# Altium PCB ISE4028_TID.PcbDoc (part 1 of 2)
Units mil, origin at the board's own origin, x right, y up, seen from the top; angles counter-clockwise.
Board outline 4000 x 3450 mil, 4 copper layers (Layer 1 - Top Layer, Layer 2 - GND, Layer 3 - PWR, Layer 4 - Bottom Layer), stack 61.434 mil thick; 151 components, 89 nets, 421 pads, 328 vias.
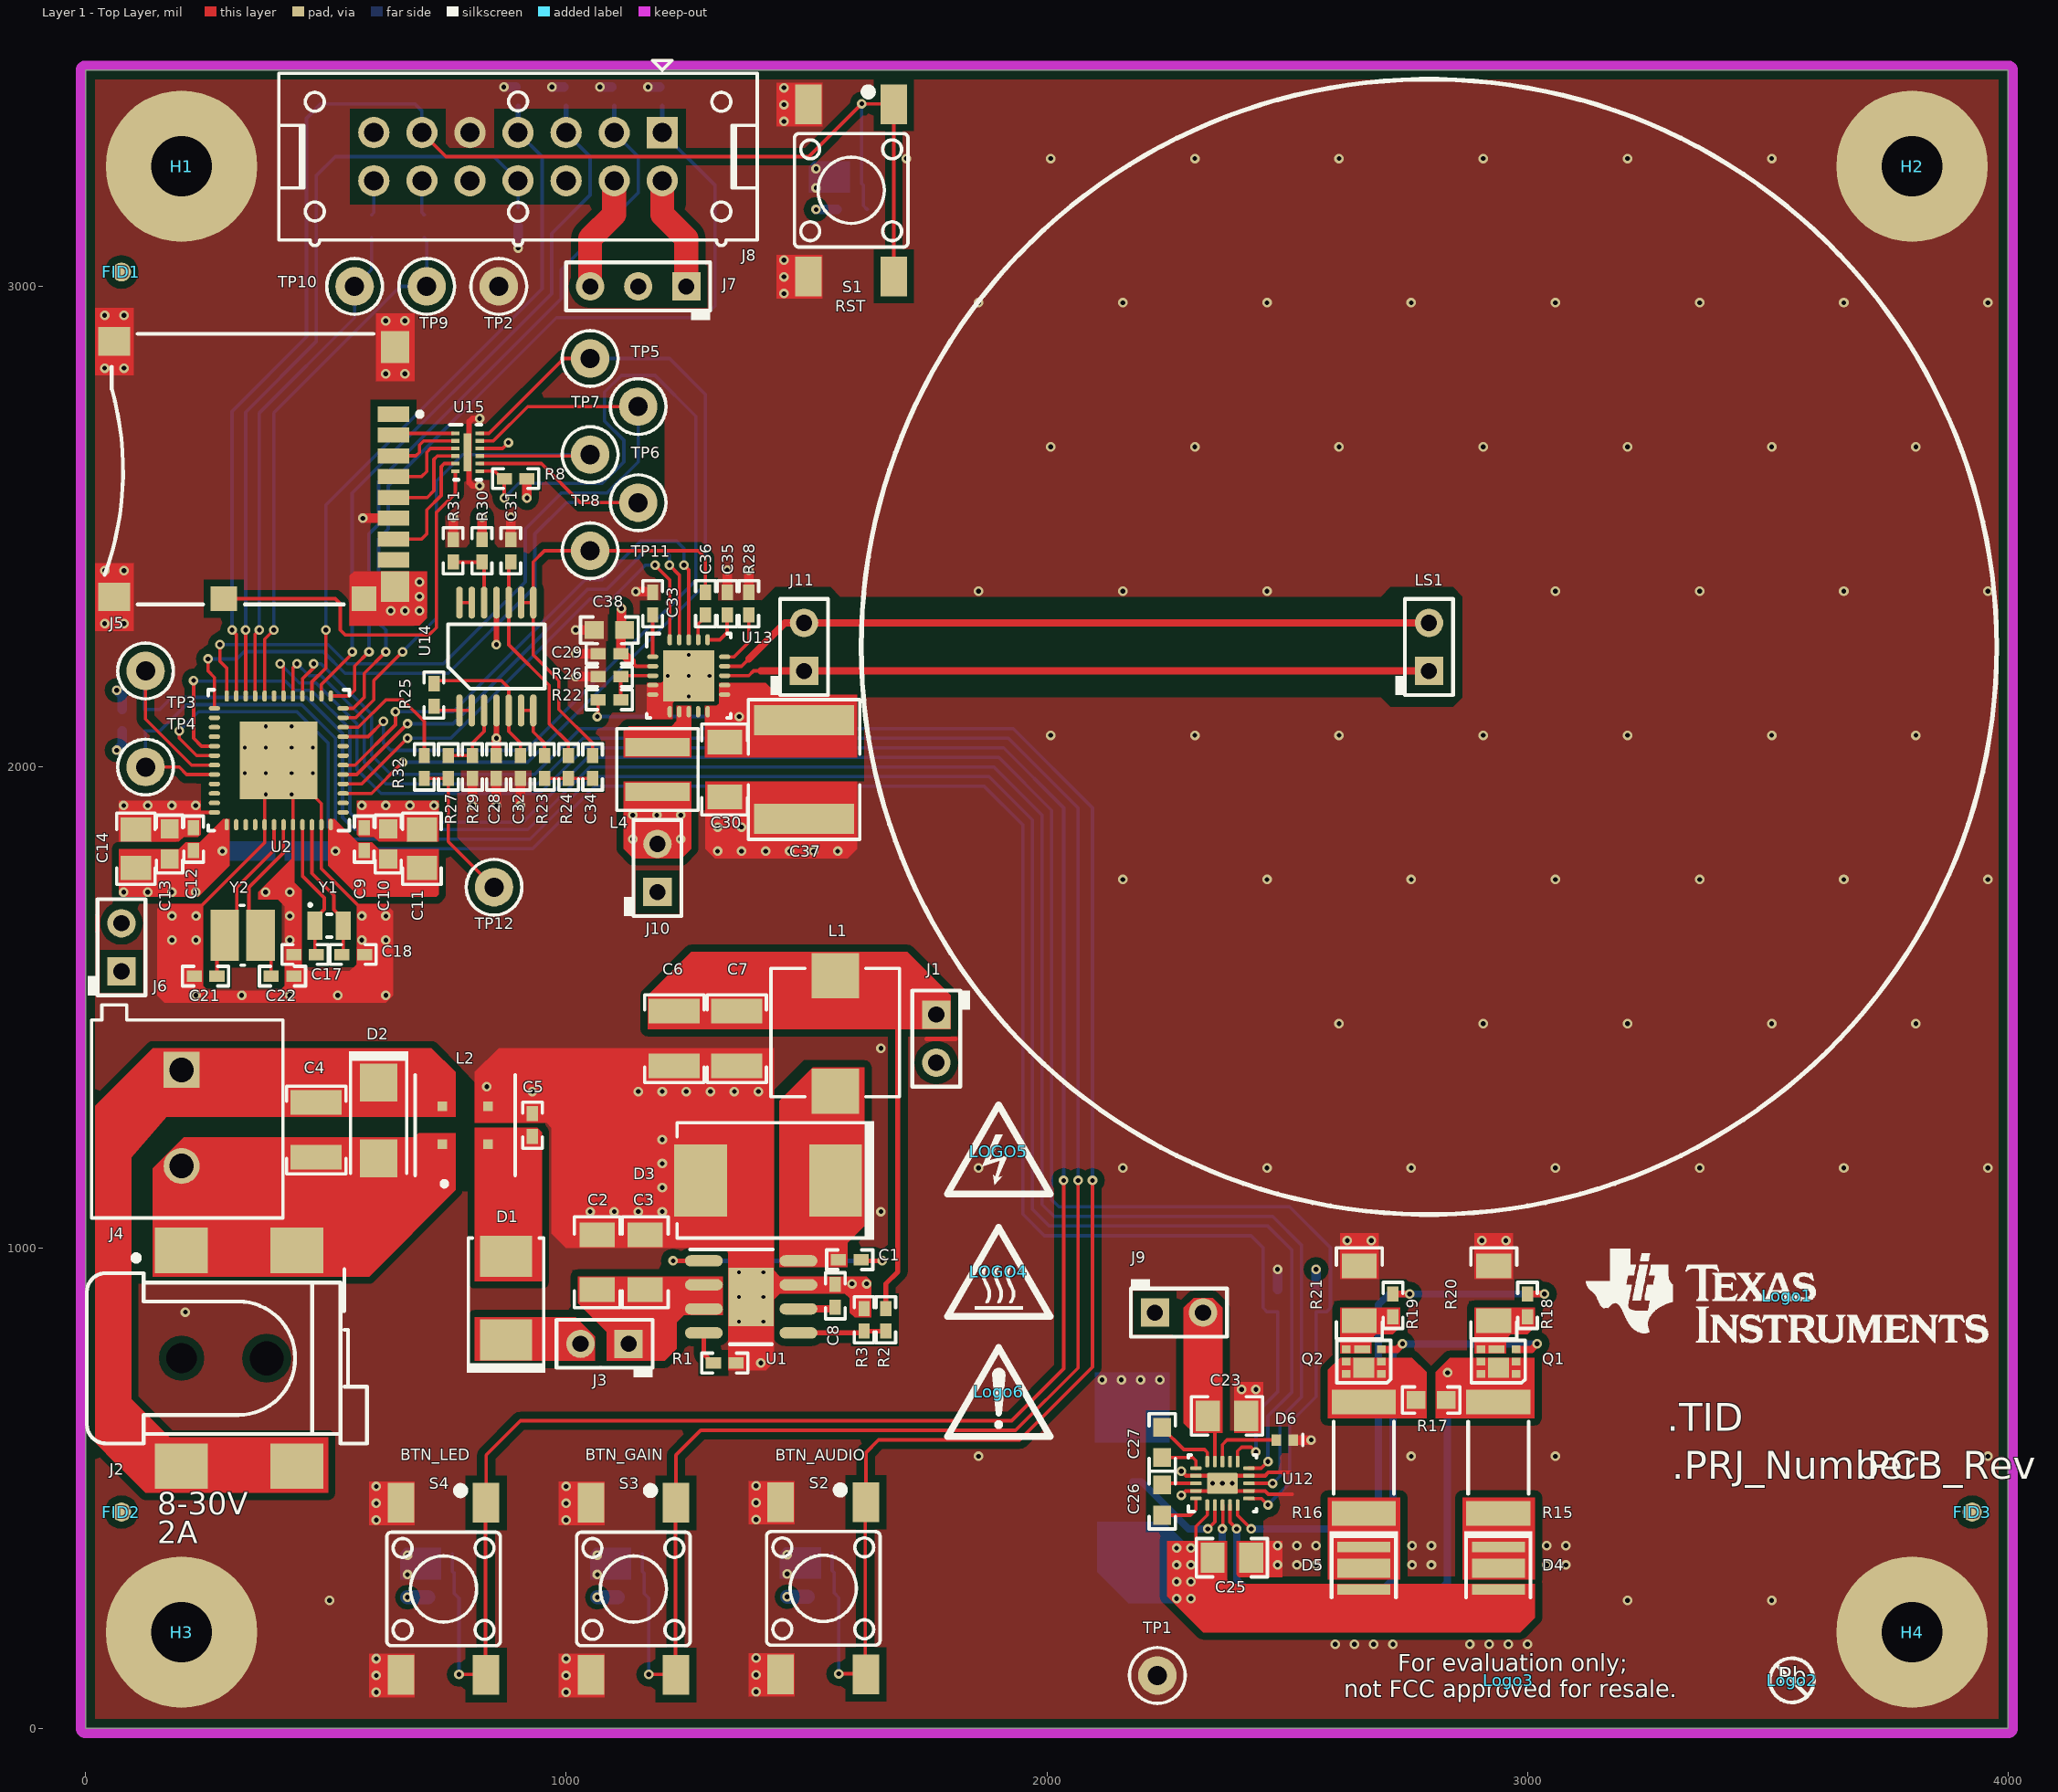
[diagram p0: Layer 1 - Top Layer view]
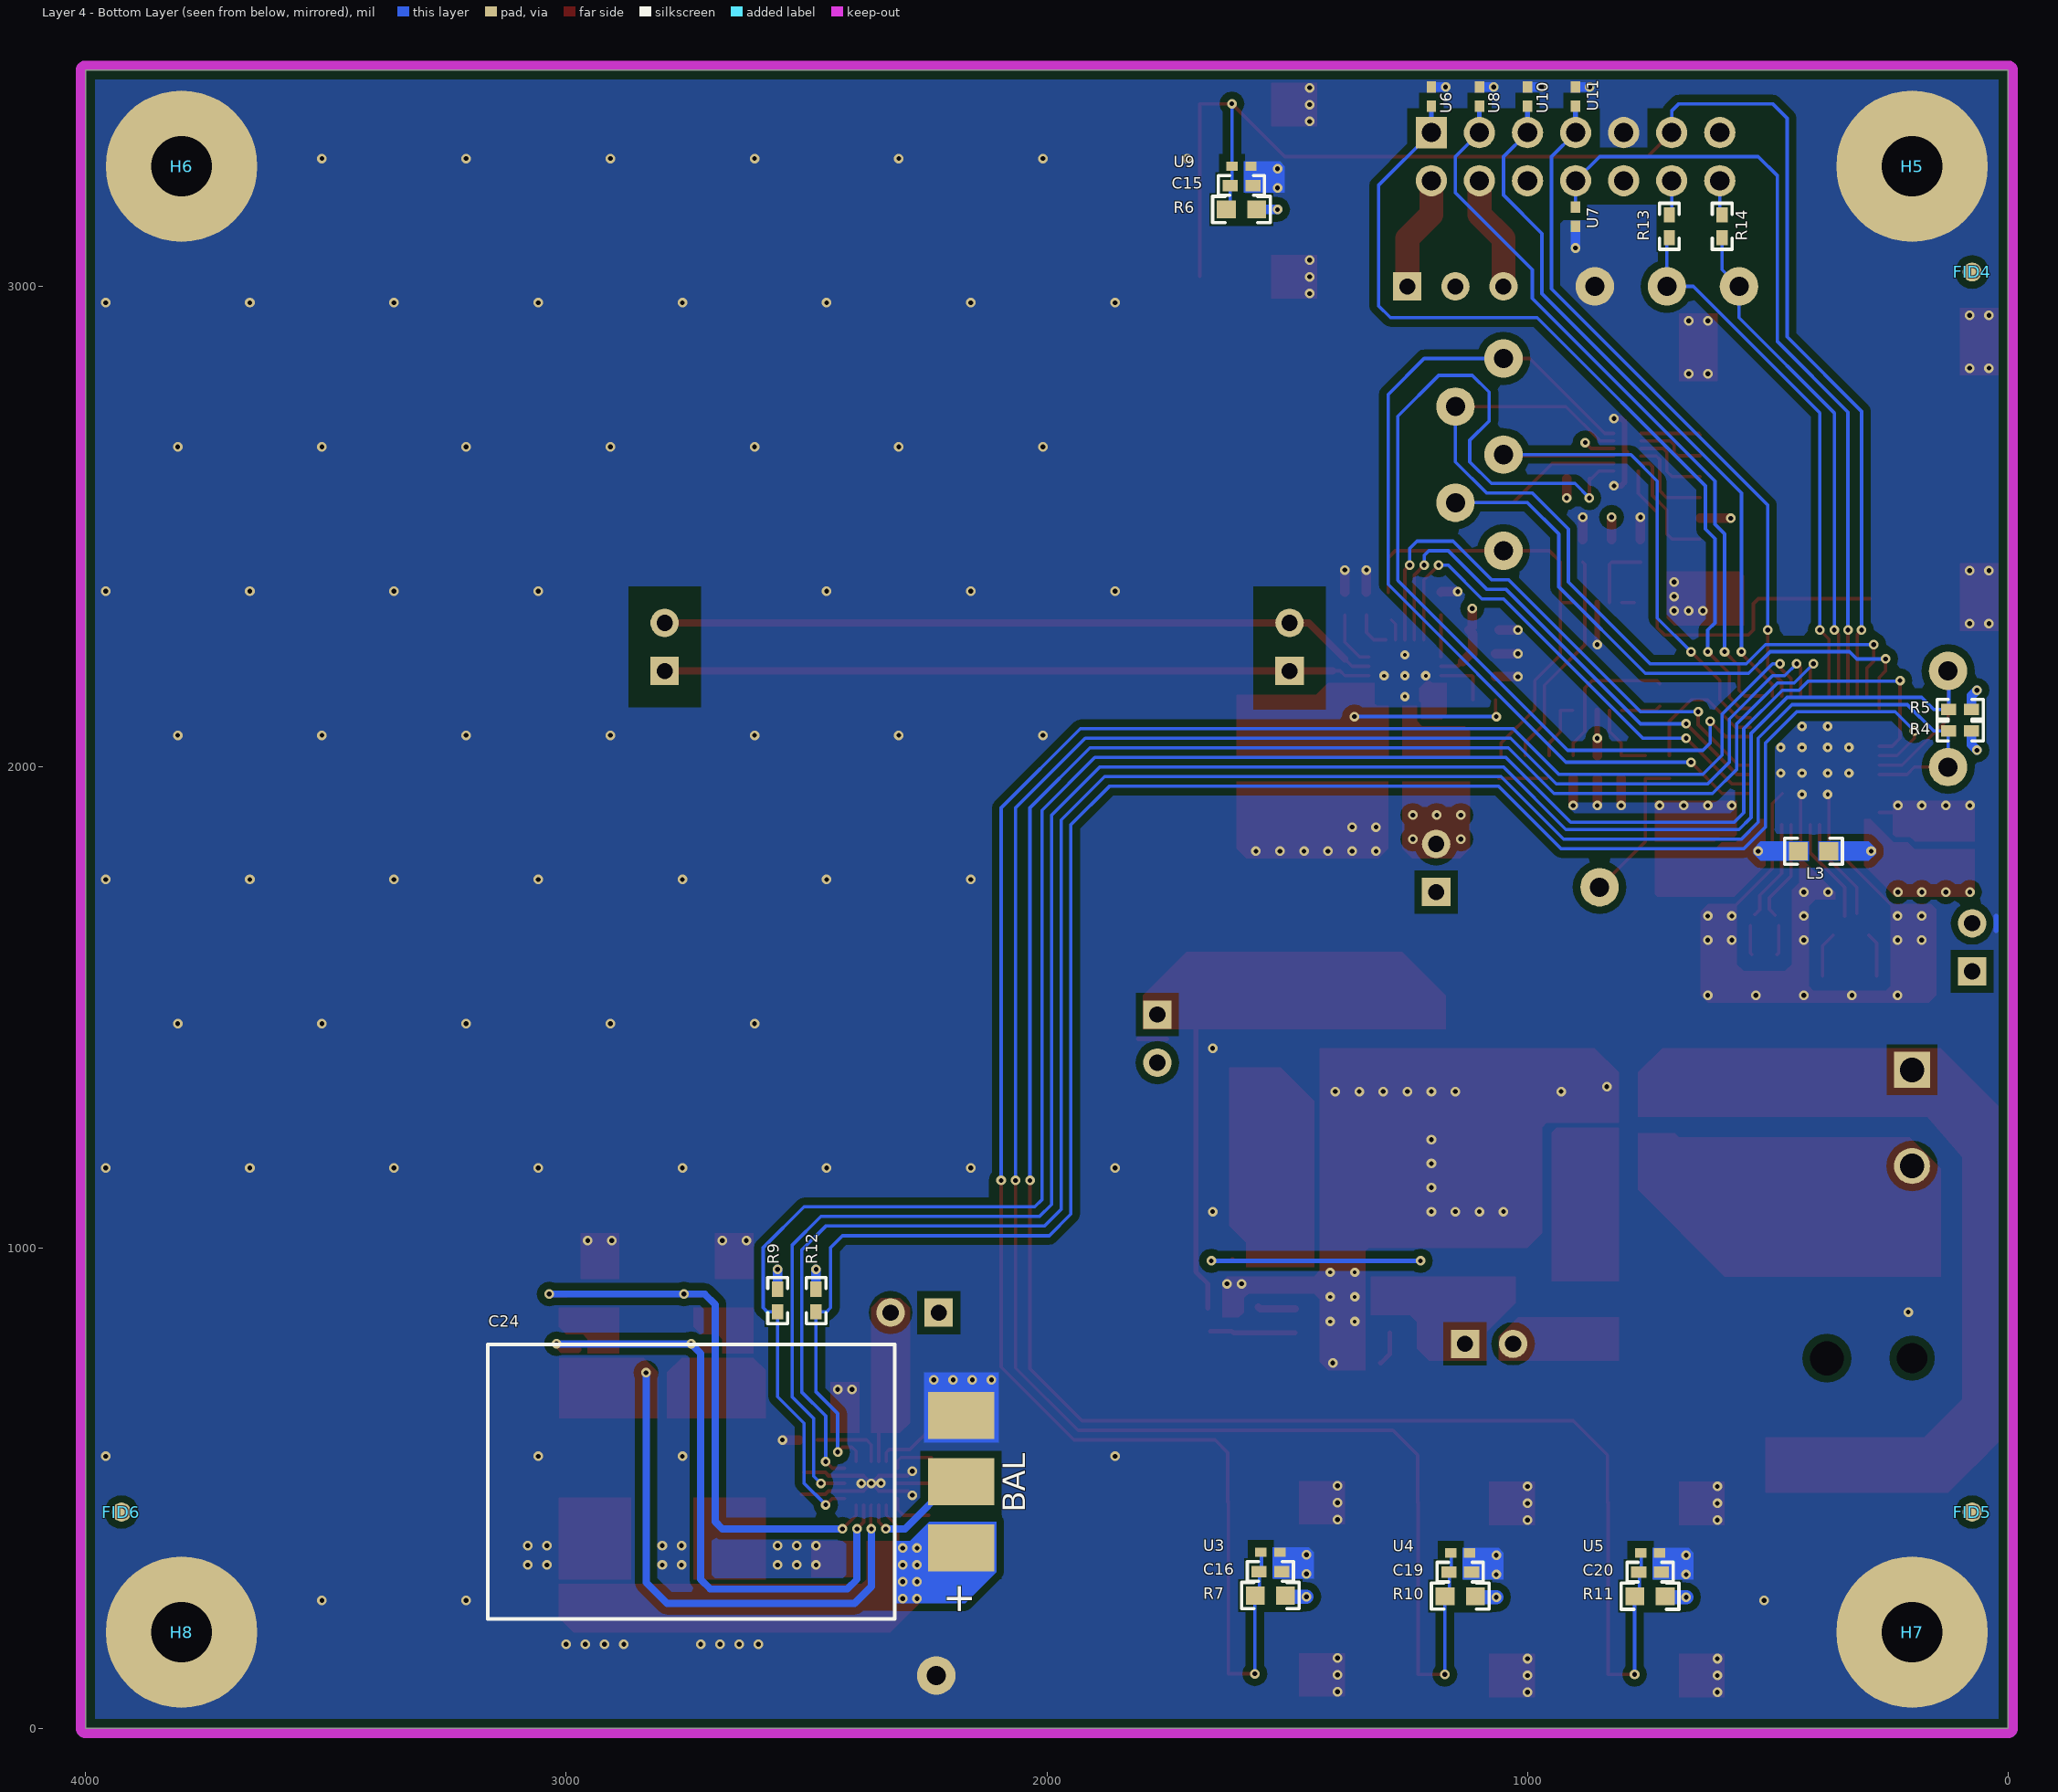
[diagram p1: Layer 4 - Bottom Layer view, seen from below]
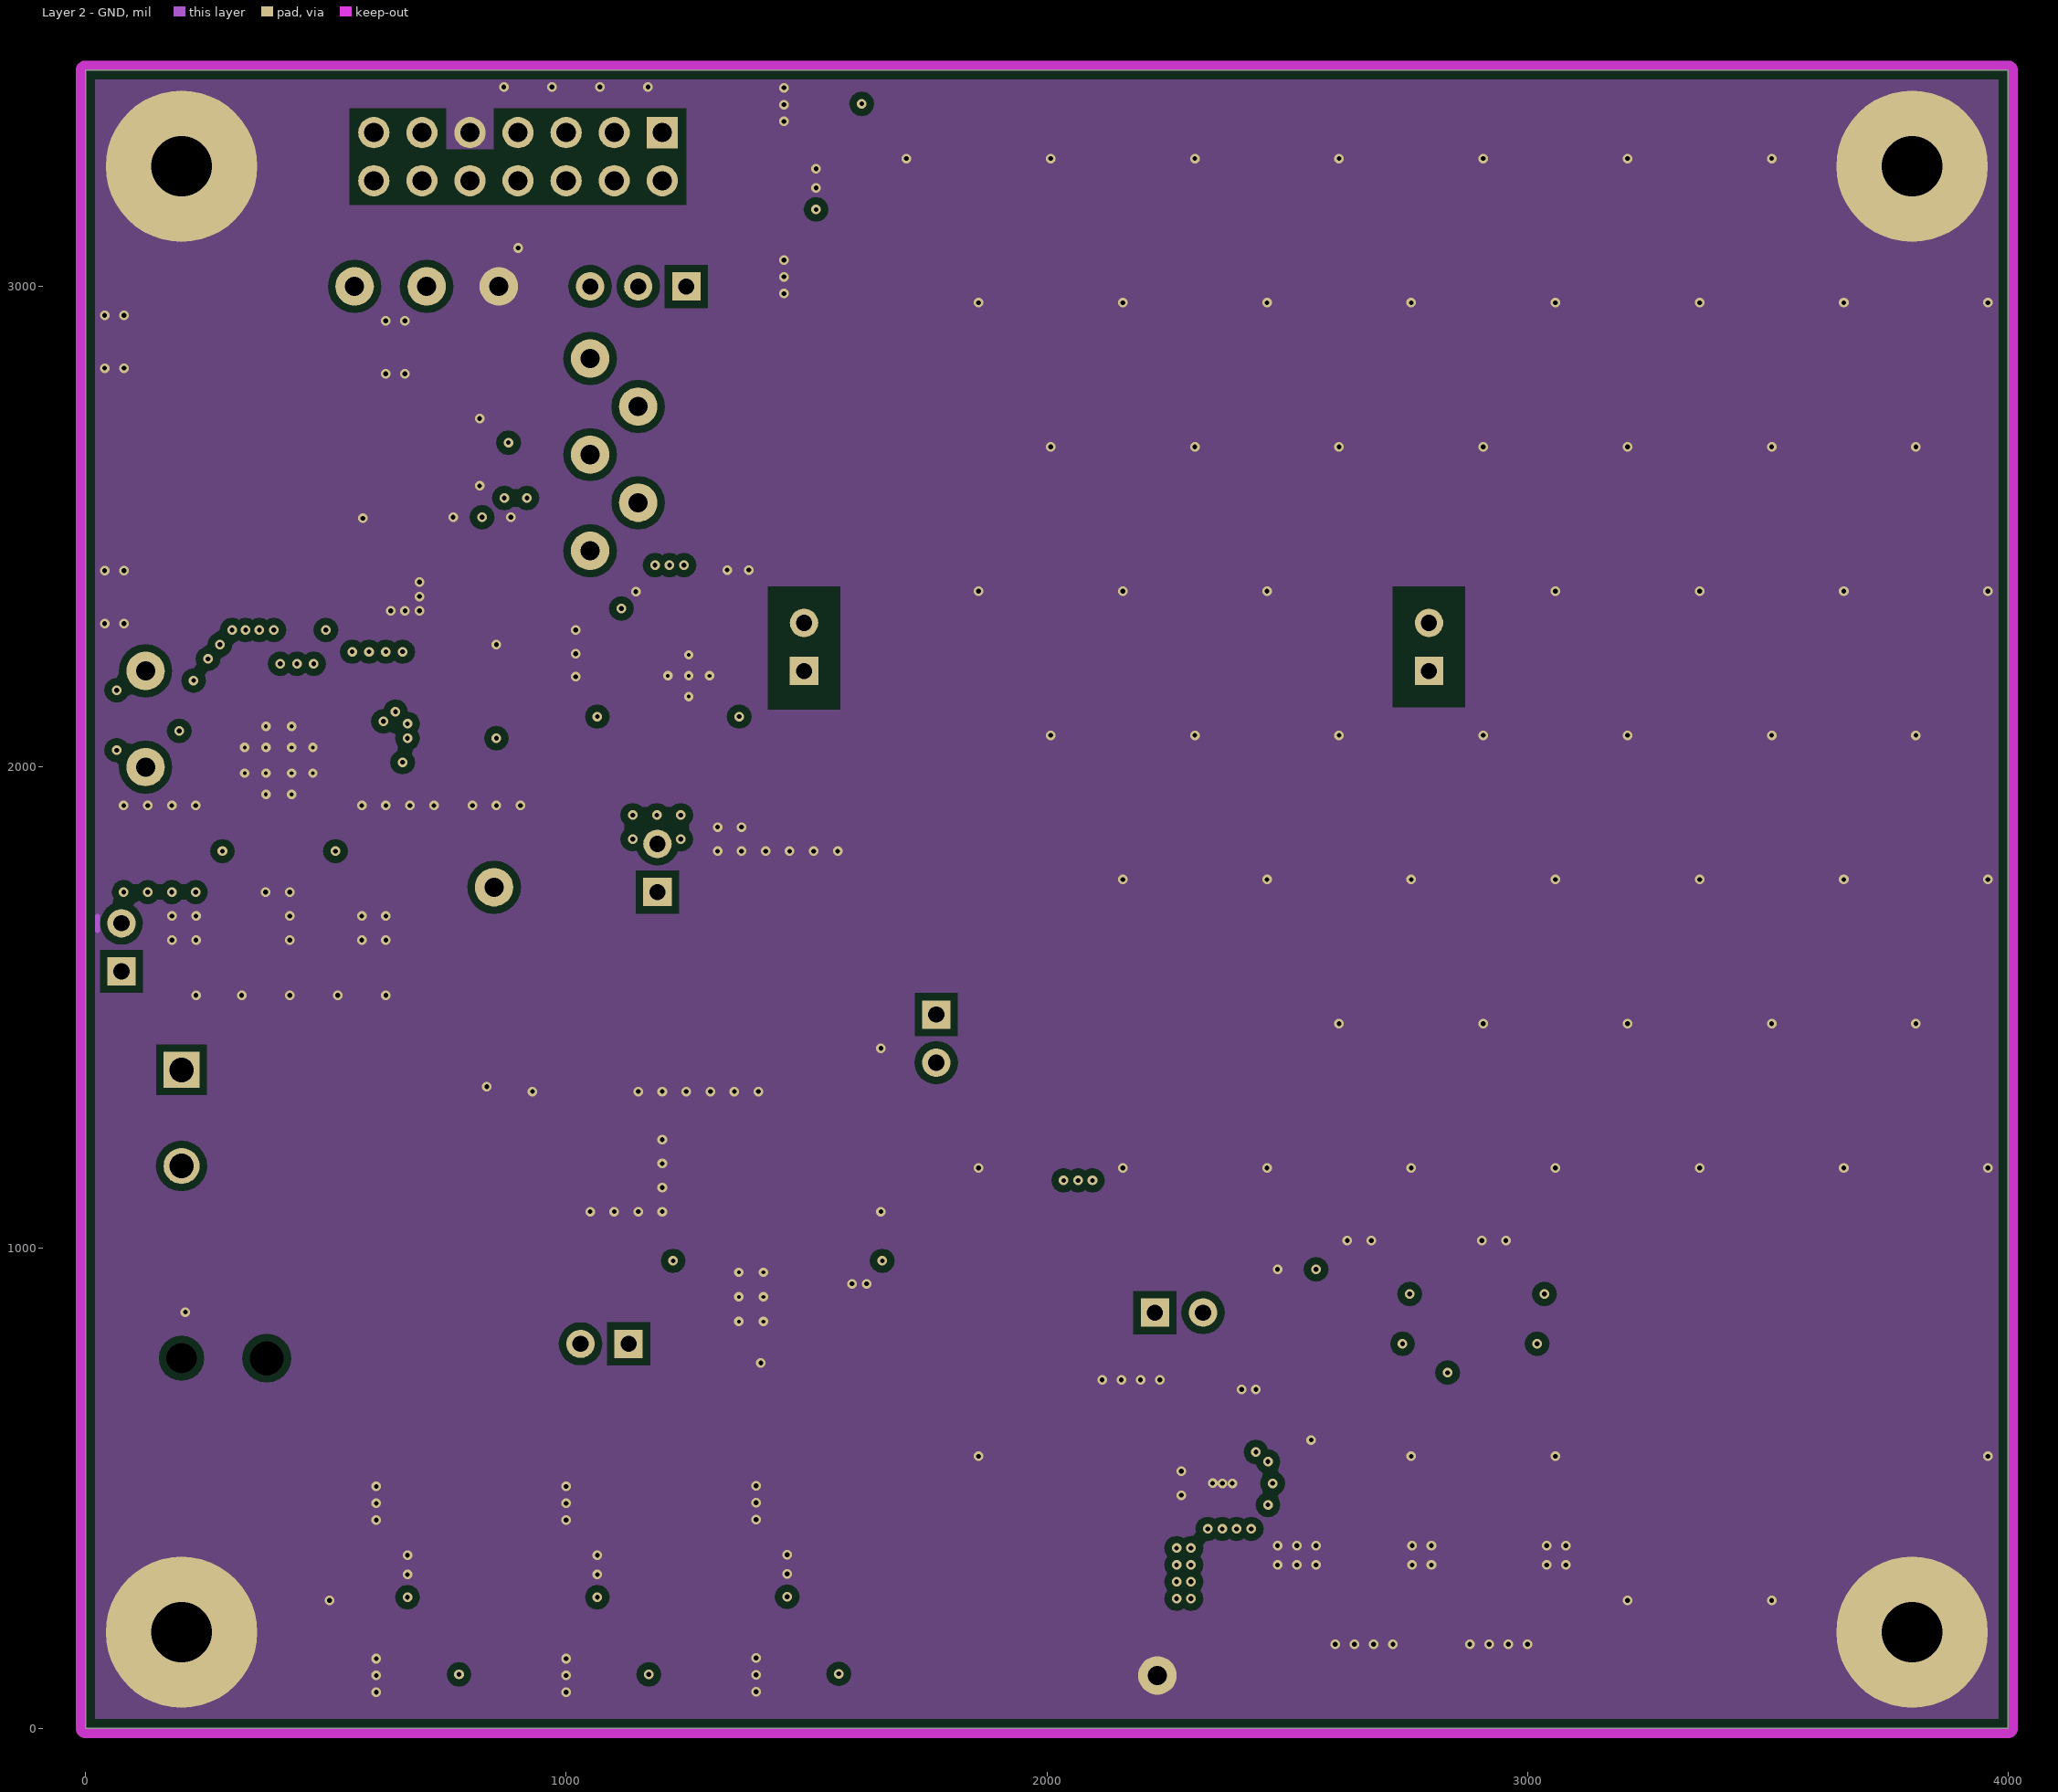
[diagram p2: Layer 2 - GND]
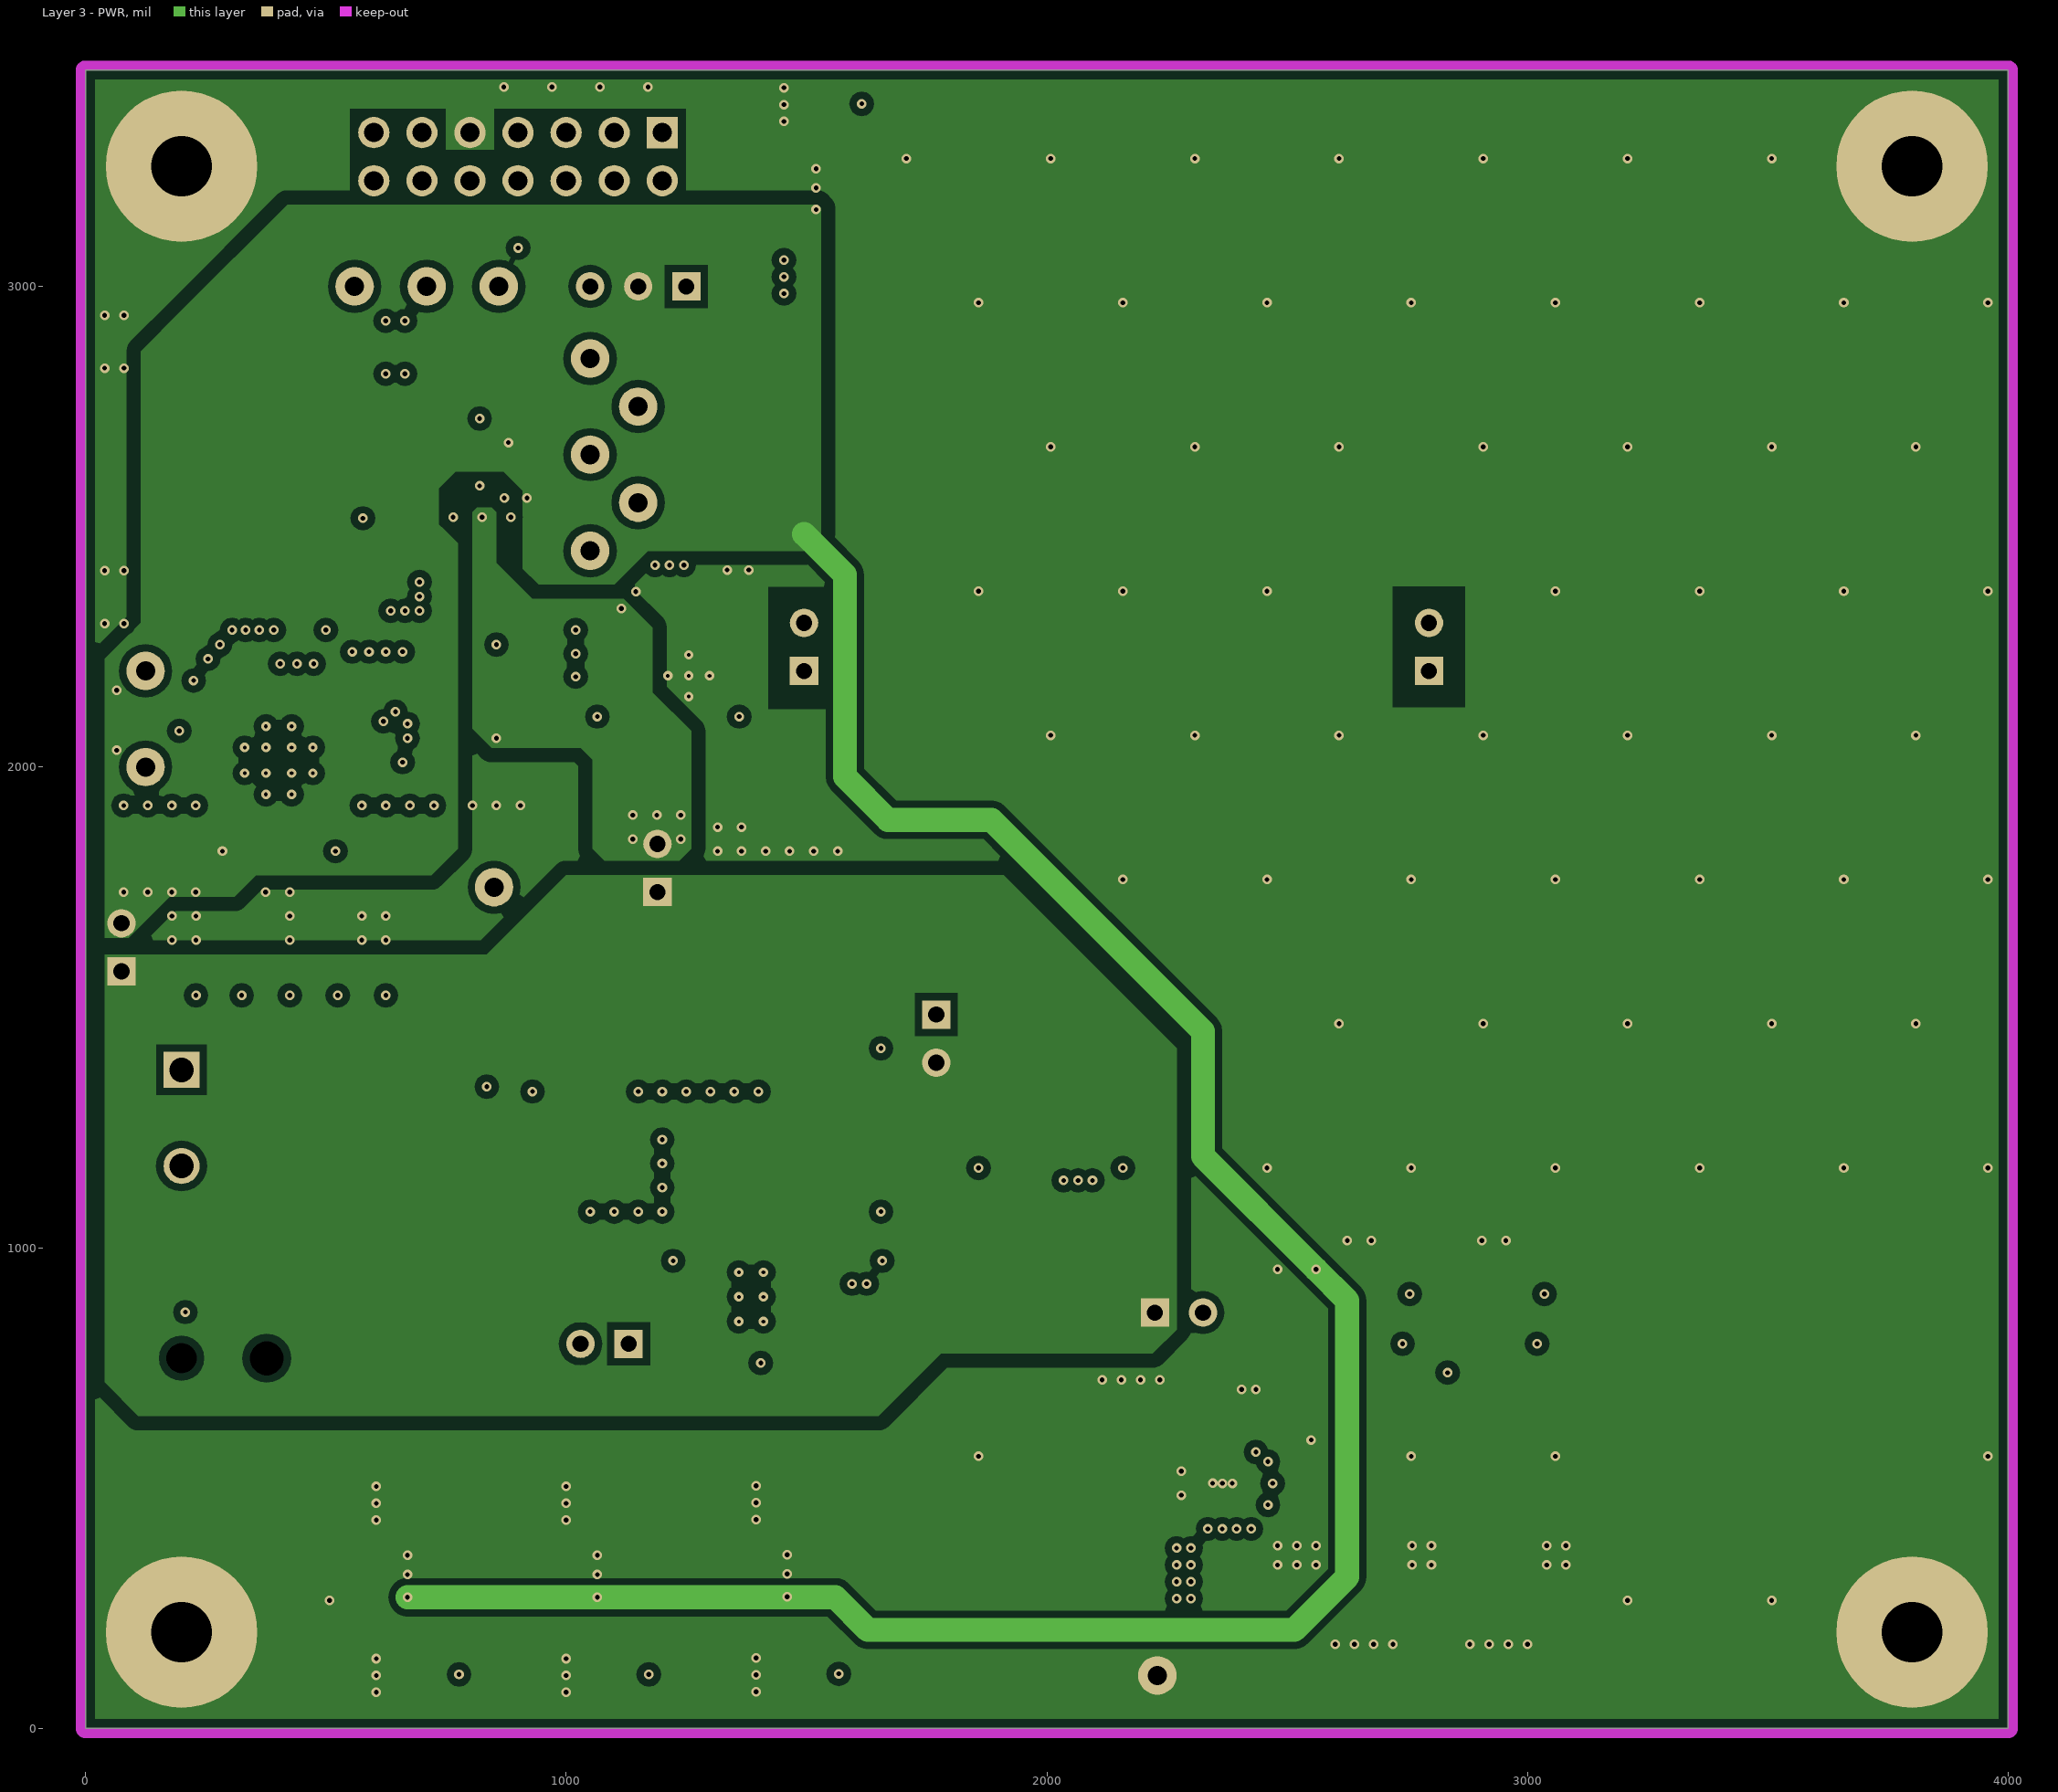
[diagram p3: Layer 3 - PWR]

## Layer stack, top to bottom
Top Solder: solder mask 0.4, Solder Resist, Dk 3.5
Layer 1 - Top Layer: signal copper 1.4
Dielectric 1: prepreg 18.6, 370HR, Dk 4.2
Layer 2 - GND: signal copper 1.417
Dielectric 2: core 18.6, 370HR, Dk 4.8
Layer 3 - PWR: signal copper 1.417
Dielectric 3: prepreg 18.6, 370HR, Dk 4.2
Layer 4 - Bottom Layer: signal copper 1.4
Bottom Solder: solder mask 0.4, Solder Resist, Dk 3.5

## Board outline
0,0 4000,0 4000,3450 0,3450

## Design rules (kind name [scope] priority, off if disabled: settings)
AcuteAngle [All] p1: minimum=4.50000000000000E+0001 checktracksonly=FALSE
AssemblyTestPointUsage [All] p1: valid=2
Clearance Clearance_Keepouts [((IsTrack Or IsArc) And Not InPoly) And IsFree and IsKeepOut vs ((IsTrack Or IsArc) And Not InPoly) And IsFree and IsKeepOut] p1: gap=0
Clearance Clearance_BoardEdge_MountingHoles [OnCopper and InComponentClass('Mounting Holes') vs IsKeepOut] p2: gap=20
Clearance Clearance_BoardEdge_Poly [OnCopper and InPoly vs IsKeepOut] p3: gap=20
Clearance Clearance_BoardEdge [OnCopper and Not InComponentClass('Logo') and not InComponentClass('FiducialMark') and not IsKeepOut vs IsKeepOut] p4: gap=20
Clearance Clearance_Poly [InPolygon] p5: gap=15 except(30: Poly-Poly)
Clearance [All] p6: gap=7.5
ComponentClearance "CONN_SBH11-PBPC-D07-ST-BK Clearance" [HasFootprint('CONN_SBH11-PBPC-D07-ST-BK')] p1: gap=0 collisioncheckmode=3 verticalgap=10 showdistances=FALSE
ComponentClearance "DPY0002A Clearance" [HasFootprint('DPY0002A')] p2: gap=0 collisioncheckmode=3 verticalgap=10 showdistances=FALSE
ComponentClearance ComponentClearance_MountingHoles_FiducialMarks [InComponentClass('Mounting Holes') vs InComponentClass('FiducialMark')] p3: gap=50 collisioncheckmode=3 verticalgap=10 showdistances=TRUE
ComponentClearance ComponentClearance_Shunt [InComponentClass('Header') vs InComponentClass('Shunt')] p4: gap=0 collisioncheckmode=3 verticalgap=0 showdistances=TRUE
ComponentClearance ComponentClearance_Logo [InComponentClass(Logo)] p5: gap=50 collisioncheckmode=3 verticalgap=10 showdistances=TRUE
ComponentClearance ComponentClearance_ScrewToNut [(HasFootprint('NY PMS 440 0025 PH')) vs (HasFootprint('Keystone_1902C'))] p6: gap=5 collisioncheckmode=3 verticalgap=10 showdistances=TRUE
ComponentClearance ComponentClearance_MountingHoles [InComponentClass('Mounting Holes')] p7: gap=50 collisioncheckmode=3 verticalgap=100000 showdistances=TRUE
ComponentClearance ComponentClearance_SmallPassives [HasFootprint('0201*') or HasFootprint('0402*') or HasFootprint('0508') or HasFootprint('0603*') or HasFootprint('0612') or HasFootprint('0805*') or HasFootprint('0815*') or HasFootprint('0830*') or HasFootprint('1206*') or HasFootprint('1210*') or HasFootprint('1808*') or HasFootprint('1812*') or HasFootprint('1825*') or HasFootprint('2010*') or HasFootprint('2220*') or HasFootprint('2225*') or HasFootprint('2512*') or HasFootprint('2728*') or HasFootprint('3518*') vs HasFootprint('0201*') or HasFootprint('0402*') or HasFootprint('0508') or HasFootprint('0603*') or HasFootprint('0612') or HasFootprint('0805*') or HasFootprint('0815*') or HasFootprint('0830*') or HasFootprint('1206*') or HasFootprint('1210*') or HasFootprint('1808*') or HasFootprint('1812*') or HasFootprint('1825*') or HasFootprint('2010*') or HasFootprint('2220*') or HasFootprint('2225*') or HasFootprint('2512*') or HasFootprint('2728*') or HasFootprint('3518*')] p8: gap=5 collisioncheckmode=3 verticalgap=10 showdistances=TRUE
ComponentClearance ComponentClearance_THtoSMT [IsThruComponent vs IsSMTComponent] p9: gap=5 collisioncheckmode=3 verticalgap=100000 showdistances=TRUE
ComponentClearance ComponentClearance_THtoTH [IsThruComponent vs IsThruComponent] p10: gap=5 collisioncheckmode=3 verticalgap=100000 showdistances=TRUE
ComponentClearance [All] p11: gap=5 collisioncheckmode=3 verticalgap=10 showdistances=TRUE
DiffPairsRouting [All] p1: maxlimit=100 minlimit=10 mostfreqgap=10 toplayer_minwidth=15 toplayer_maxwidth=15 toplayer_prefwidth=15 midlayer1_minwidth=15 midlayer1_maxwidth=15 midlayer1_prefwidth=15 midlayer2_minwidth=15 midlayer2_maxwidth=15 midlayer2_prefwidth=15 bottomlayer_minwidth=15 bottomlayer_maxwidth=15 bottomlayer_prefwidth=15 maxuncoupledlength=1000
FabricationTestPointUsage TestPointUsage [All] p1: valid=2 allowmultiple=FALSE
FabricationTestpoint Testpoint [All] p1: side=3 testpointundercomponent=TRUE minsize=40 maxsize=100 preferedsize=60 minholesize=0 maxholesize=40 preferedholesize=32 testpointgrid=1 allowsidetop=TRUE allowsidebottom=TRUE usegrid=TRUE gridtolerance=0.01
FanoutControl Fanout_LCC [IsLCC] p1: bgadir=Out bgaviamode=Centered fanoutstyle=Auto fanoutdirection=Alternating viagrid=1 // Fanout_LCC (Default Rule)
FanoutControl Fanout_BGA [IsBGA] p2: bgadir=Out bgaviamode=Centered fanoutstyle=Auto fanoutdirection=Alternating viagrid=1 // Fanout_BGA (Default Rule)
FanoutControl Fanout_Default [All] p4: bgadir=Out bgaviamode=Centered fanoutstyle=Auto fanoutdirection=Alternating viagrid=1 // Fanout_Default (Default Rule)
FanoutControl Fanout_Small [(CompPinCount < 5)] p5: bgadir=Out bgaviamode=Centered fanoutstyle=Auto fanoutdirection=OutThenIn viagrid=1 // Fanout_Small (Default Rule)
HoleSize [All] p1: absolutevalues=TRUE maxlimit=550 minlimit=5 maxpercent=80.000 minpercent=20.000
MinimumAnnularRing MinimumAnnularRing_ThermalPadVias [IsVia and InAnyComponent] p1: minimumring=5.91
MinimumAnnularRing [All] p2: minimumring=5
MinimumSolderMaskSliver SilkscreenOverComponentPads [All] p1: minsoldermaskwidth=5
MinimumSolderMaskSliver MinimumSolderMaskSliver_Logo [InComponentClass('Logo') vs InComponentClass('Logo')] p2: minsoldermaskwidth=0.7
MinimumSolderMaskSliver [All] p3: minsoldermaskwidth=5
PlaneConnect [All] p1: planeconnectstyle=Relief reliefexpansion=10 reliefentries=4 reliefconductorwidth=10 reliefairgap=10
PolygonConnect [All] p1: connectstyle=Direct reliefconductorwidth=10 reliefentries=4 polygonreliefangle="90 Angle" airgapwidth=10
RoutingVias ThermalPadVias [IsVia and InAnyComponent] p1: holewidth=7.87 width=19.68 viastyle="Through Hole" minholewidth=7.87 minwidth=19.68 maxholewidth=12.99 maxwidth=23.62
RoutingVias [All] p2: holewidth=12 width=28 viastyle="Through Hole" minholewidth=5 minwidth=20 maxholewidth=100 maxwidth=150
SMDToCorner [All] p1: distance=30000
SilkToBoardRegionClearance [Not ((IsComment or IsDesignator) And (Hide <> 'False')) and not InRegion(1000,500,4000,800)] p1:
SilkToSilkClearance SilkToSilkClearance_Pb-FreeLogo [(HasFootprint('Pb-Free_Overlay_Medium') OR HasFootprint('Pb-Free_Overlay_Small')) vs (HasFootprint('Pb-Free_Overlay_Medium') OR HasFootprint('Pb-Free_Overlay_Small'))] p1: silktosilkclearance=0
SilkToSilkClearance [All] p2: silktosilkclearance=5
SilkToSolderMaskClearance "Silk to Solder Mask Opening" [All] p1: minsilkscreentomaskgap=1 clearancetoexposedcopper=FALSE
SolderMaskExpansion [All] p1: expansion=3
UnpouredPolygon [All] p1: allowunpoured=FALSE
Width [All] p1: maxlimit=100 minlimit=6 preferedwidth=10 checkconnectedcopper=TRUE
14 further rules are at their usual default settings.

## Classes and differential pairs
component class ISE4028_PWR_MCU: C1 C2 C3 C4 C5 C6 C7 C8 C9 C10 C11 C12 C13 C14 C15 C16 C17 C18 C19 C20 C21 C22 D1 D2 D3 J1 J2 J3 J4 J5 J6 J7 J8 L1 L2 L3 R1 R2 R3 R4 R5 R6 R7 R8 R9 R10 R11 R12 R13 R14 R32 S1 S2 S3 S4 TP1 TP2 TP3 TP4 TP5 TP6 TP7 TP8 TP9 TP10 U1 U2 U3 U4 U5 U6 U7 U8 U9 U10 U11 U15 Y1 Y2
component class ISE4028_PIEZO_LED: C23 C24 C25 C26 C27 C28 C29 C30 C31 C32 C33 C34 C35 C36 C37 C38 D4 D5 D6 J9 J10 J11 L4 LS1 Q1 Q2 R15 R16 R17 R18 R19 R20 R21 R22 R23 R24 R25 R26 R27 R28 R29 R30 R31 TP11 TP12 U12 U13 U14
component class Header: J1 J3 J6 J9 J10 J11 LS1
component class "Mounting Holes": H1 H2 H3 H4
component class Logo: Logo1
component class ISE4028_TID_Hardware: FID1 FID2 FID3 FID4 FID5 FID6 H1 H2 H3 H4 H5 H6 H7 H8 Logo1 Logo2 Logo3 LOGO4 LOGO5 Logo6 ZZ1 ZZ2 ZZ3 ZZ4
component class FiducialMark: FID1 FID2 FID3 FID4 FID5 FID6
component class AssemblyNote: ZZ1 ZZ2 ZZ3 ZZ4

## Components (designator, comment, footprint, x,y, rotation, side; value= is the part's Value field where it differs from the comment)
C1 "C1005X7R1H104K" 0402 1590,975 r0 top
C2 "GRM31CR71H475KA12L" 1206 1064.57,969.49 r90 top
C3 "GRM31CR71H475KA12L" 1206 1164.57,969.49 r90 top
C4 "C1210C102KGRACTU" 1210 480,1245 r270 top
C5 "C1005X7R1H104K" 0402 930,1255 r90 top
C6 "GRM32ER71A476KE15L" 1210 1225,1435 r270 top
C7 "GRM32ER71A476KE15L" 1210 1355,1435 r270 top
C8 "GRM155R71C823KA88D" 0402 1560,900 r90 top
C9 "GRM155R71C104KA88D" 0402 580,1850 r270 top
C10 "C1608X7R1C105K" 0603 630,1840 r270 top
C11 "C2012X7R0J106M125AB" 0805_HV 700,1830 r90 top
C12 "GRM155R71C104KA88D" 0402 225,1850 r270 top
C13 "C1608X7R1C105K" 0603 175,1840 r270 top
C14 "C2012X7R0J106M125AB" 0805_HV 105,1830 r90 top
C15 "C1005X7R1H222K" 0402 1595,3210 r180 bottom
C16 "C1005X7R1H222K" 0402 1535,326.3 r180 bottom
C17 "GRM1555C1E120JA01D" 0402 457,1610 r180 top
C18 "GRM1555C1E120JA01D" 0402 557,1610 r0 top
C19 "C1005X7R1H222K" 0402 1140,325 r180 bottom
C20 "C1005X7R1H222K" 0402 745,325 r180 bottom
C21 "GRM1555C1H100JA01D" 0402 250,1565 r180 top
C22 "GRM1555C1H100JA01D" 0402 410,1565 r0 top
C23 "C2012X7R1A475M" 0805_HV 2375,650 r0 top
C24 "DMF3Z5R5H474M3DTA0" DMF_2100x1400 2739.45,513.03 r0 bottom locked
C25 "C2012X7R1C225K" 0805_HV 2385,355 r0 top
C26 "C1608X7R1C105K" 0603 2240,475 r90 top
C27 "C1608X7R1C105K" 0603 2240,595 r270 top
C28 "C1005X7R1C103K" 0402 855,2000 r270 top
C29 "C1005X7R1H104K" 0402 1090,2235.96 r0 top
C30 "C3216X7R2E104K" 1206 1330,1995 r270 top
C31 "C1005X7R1C103K" 0402 885,2450 r90 top
C32 "C1005X7R1C103K" 0402 905,2000 r270 top
C33 "C1005X7R1H104K" 0402 1180,2340 r270 top
C34 "C1005X7R1C473K" 0402 1055,2000 r270 top
C35 "C1005X7R1H104K" 0402 1335,2340 r90 top
C36 "C1005X7R1H104K" 0402 1290,2340 r90 top
C37 "GRM55DR72E105KW01L" 2220 1495,1995 r270 top
C38 "C1608X7R1C105K" 0603 1090,2285 r180 top
D1 "B240-13-F" SMB 875,895 r90 top
D2 "SMAJ36CA" SMA 610,1265 r270 top
D3 "B560C-13-F" SMC 1420,1140 r180 top
D4 "GW CSSRM1.PC-MTNP-5L7N-1" "GW CSSRM1_PC_White" 2939.45,333.03 r180 top
D5 "GW CSSRM1.PC-MTNP-5L7N-1" "GW CSSRM1_PC_White" 2659.45,333.03 r180 top
D6 "SML-P12UTT86" SML-P1_RED 2495,600 r180 top
FID1 "Fiducial" Fiducial10-20 75,3030 r0 top
FID2 "Fiducial" Fiducial10-20 75,450 r0 top
FID3 "Fiducial" Fiducial10-20 3925,450 r0 top
FID4 "Fiducial" Fiducial10-20 75,3030 r0 bottom
FID5 "Fiducial" Fiducial10-20 75,450 r0 bottom
FID6 "Fiducial" Fiducial10-20 3925,450 r0 bottom
H1 "NY PMS 440 0025 PH" "NY PMS 440 0025 PH" 200,3250 r0 top locked
H2 "NY PMS 440 0025 PH" "NY PMS 440 0025 PH" 3800,3250 r0 top locked
H3 "NY PMS 440 0025 PH" "NY PMS 440 0025 PH" 200,200 r0 top locked
H4 "NY PMS 440 0025 PH" "NY PMS 440 0025 PH" 3800,200 r0 top locked
H5 "1902C" Keystone_1902C 200,3250 r180 bottom locked
H6 "1902C" Keystone_1902C 3800,3250 r180 bottom locked
H7 "1902C" Keystone_1902C 200,200 r180 bottom locked
H8 "1902C" Keystone_1902C 3800,200 r180 bottom locked
J1 "800-10-002-10-001000" Mill-Max_800-10-002-10-001000 1770,1435 r270 top
J2 "PJ-002AH-SMT-TR" CUI_PJ-002AH-SMT 320,770 r0 top
J3 "800-10-002-10-001000" Mill-Max_800-10-002-10-001000 1080,800 r180 top
J4 "1715721" PhoenixContact_1715721 200,1270 r270 top
J5 "502774-0891" Molex_502774-0891 350,2620 r270 top
J6 "800-10-002-10-001000" Mill-Max_800-10-002-10-001000 75,1625 r90 top
J7 "800-10-003-10-001000" Mill-Max_800-10-003-10-001000 1150,3000 r180 top
J8 "SBH11-PBPC-D07-ST-BK" CONN_SBH11-PBPC-D07-ST-BK 900,3270 r180 top
J9 "800-10-002-10-001000" Mill-Max_800-10-002-10-001000 2275,865 r0 top
J10 "800-10-002-10-001000" Mill-Max_800-10-002-10-001000 1190,1790 r90 top
J11 "800-10-002-10-001000" Mill-Max_800-10-002-10-001000 1495,2250 r90 top
L1 "SRP7030-4R7FM" SRP7030F_3 1559.96,1447.73 r90 top
L2 "DLW5BTM102TQ2K" DLW5BT_TQ2 790,1255 r90 top
L3 "BLM18SG331TN1D" 0603 405,1825 r0 bottom
L4 "XFL4020-472MEB" XFL4020 1190,1995 r270 top
Logo1 "Texas Instruments" TI_Stacked_Overlay_Small 3540,900 r0 top
Logo2 "Pb-Free Symbol" Pb-Free_Overlay_Small 3550,100 r0 top
Logo3 "FCC disclaimer" FCC_disclaimer_stacked 2960,100 r0 top
LOGO4 "CAUTION HOT SURFACE" IEC_HotSurface_Small 1900,950 r0 top
LOGO5 "DANGER HIGH VOLTAGE" IEC_HighVoltage_Small 1900,1200 r0 top
Logo6 "CAUTION.  READ USER GUIDE BEFORE USE" IEC_Caution_Small 1900,700 r0 top
LS1 "800-10-002-10-001000" Mill-Max_800-10-002-10-001000 2795,2250 r90 top
Q1 "CSD15571Q2" TRANS_NexFET_Q2 2939.45,763.03 r180 top
Q2 "CSD15571Q2" TRANS_NexFET_Q2 2659.45,763.03 r180 top
R1 "CRCW040228K0FKED" 0402 1330,760 r0 top
R2 "CRCW040234K0FKED" 0402 1665,850 r90 top
R3 "CRCW040210K0FKED" 0402 1620,850 r270 top
R4 "CRCW040210K0FKED" 0402 100,2075 r180 bottom
R5 "CRCW040210K0FKED" 0402 100,2120 r180 bottom
R6 "CRCW060347K5FKEA" 0603 1595,3160 r180 bottom
R7 "CRCW060347K5FKEA" 0603 1535,276.3 r180 bottom
R8 "CRCW0402100KFKED" 0402 895,2600 r0 top
R9 "CRCW040210K0FKED" 0402 2560,890 r90 bottom
R10 "CRCW060347K5FKEA" 0603 1140,275 r180 bottom
R11 "CRCW060347K5FKEA" 0603 745,275 r180 bottom
R12 "CRCW040210K0FKED" 0402 2480,890 r270 bottom
R13 "CRCW04020000Z0ED" 0402 705,3125 r90 bottom
R14 "CRCW04020000Z0ED" 0402 595,3125 r90 bottom
R15 "CRCW25120000Z0EG" 2512 2939.45,563.03 r270 top
R16 "CRCW25120000Z0EG" 2512 2659.45,563.03 r270 top
R17 "CRCW06030000Z0EA" 0603 2799.45,683.03 r180 top
R18 "CRCW04020000Z0ED" 0402 3000,880 r270 top
R19 "CRCW04020000Z0ED" 0402 2720,880 r270 top
R20 "CSR1206FK75L0" 1206 2930,905 r270 top
R21 "CSR1206FK75L0" 1206 2650,905 r270 top
R22 "CRCW0402909KFKED" 0402 1090,2140 r180 top
R23 "CRCW04021K21FKED" 0402 955,2000 r270 top
R24 "CRCW04022K74FKED" 0402 1005,2000 r90 top
R25 "CRCW04024K02FKED" 0402 725,2150 r90 top
R26 "CRCW040218K7FKED" 0402 1090,2187.98 r0 top
R27 "CRCW040212K4FKED" 0402 755,2000 r90 top
R28 "CRCW04026K98FKED" 0402 1380,2340 r270 top
R29 "CRCW04026K19FKED" 0402 805,2000 r90 top
R30 "CRCW0402100KFKED" 0402 825,2450 r90 top
R31 "CRCW0402100KFKED" 0402 765,2450 r270 top
R32 "CRCW04020000Z0ED" 0402 705,2000 r270 top
S1 "4-1437565-1" SW_FSM4JSMA 1593.05,3200 r0 top
S2 "4-1437565-1" SW_FSM4JSMA 1535,291.3 r0 top
S3 "4-1437565-1" SW_FSM4JSMA 1140,290 r0 top
S4 "4-1437565-1" SW_FSM4JSMA 745,290 r0 top
TP1 "5001" Keystone5001 2230,110 r0 top
TP2 "5001" Keystone5001 860,3000 r0 top
TP3 "5004" Keystone5004 125,2200 r0 top
TP4 "5004" Keystone5004 125,2000 r0 top
TP5 "5003" Keystone5003 1050,2850 r0 top
TP6 "5003" Keystone5003 1050,2650 r0 top
TP7 "5003" Keystone5003 1150,2750 r0 top
TP8 "5003" Keystone5003 1150,2550 r0 top
TP9 "5004" Keystone5004 710,3000 r0 top
TP10 "5004" Keystone5004 560,3000 r0 top
TP11 "5002" Keystone5002 1050,2450 r0 top
TP12 "5002" Keystone5002 850,1750 r0 top
U1 "LMR14030SDDAR" DDA0008E_N 1384.96,897.73 r0 top
U2 "MSP430FR5969IRGZ" RGZ0048B 402.29,2013.97 r180 top
U3 "TPD1E10B06DPYR" DPY0002A 1535,366.3 r180 bottom
U4 "TPD1E10B06DPYR" DPY0002A 1140,365 r180 bottom
U5 "TPD1E10B06DPYR" DPY0002A 745,365 r180 bottom
U6 "TPD1E10B06DPYR" DPY0002A 1200,3395 r90 bottom
U7 "TPD1E10B06DPYR" DPY0002A 900,3145 r270 bottom
U8 "TPD1E10B06DPYR" DPY0002A 1100,3395 r90 bottom
U9 "TPD1E10B06DPYR" DPY0002A 1595,3250 r180 bottom
U10 "TPD1E10B06DPYR" DPY0002A 1000,3395 r90 bottom
U11 "TPD1E10B06DPYR" DPY0002A 900,3395 r90 bottom
U12 "LM3550SPX/NOPB" NHU0020A 2365.37,509.72 r90 top
U13 "DRV2700RGPR" RGP0020D 1255,2190 r0 top
U14 "LMV344IPW" PW0014A_N 855,2230 r90 top
U15 "TPD6F003DQDR" DQD0012A 795,2655 r0 top
Y1 "CM8V–T1A 32.768kHz 9.0pF +/-20ppm TA QC" MC_CM8V-T1A 507,1670 r0 top
Y2 "NX3225GD-8MHZ-STD-CRA-3" NDK_NX3225GD 327,1650 r0 top
ZZ1 "These assemblies are ESD sensitive, ESD precautions shall be observed." AssemblyNote 200,4000 r0 top
ZZ2 "These assemblies must be clean and free from flux and all contaminants. Use of no clean flux is not acceptable." AssemblyNote 200,3900 r0 top
ZZ3 "These assemblies must comply with workmanship standards IPC-A-610 Class 2, unless otherwise specified." AssemblyNote 200,3800 r0 top
ZZ4 "Jumpers should be placed on J1, J3, J6, J7 (pins 2-3), J9, and J10." AssemblyNote 200,3700 r0 top

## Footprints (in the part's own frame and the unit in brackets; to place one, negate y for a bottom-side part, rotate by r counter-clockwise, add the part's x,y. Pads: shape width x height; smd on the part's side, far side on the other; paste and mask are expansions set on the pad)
0402 [mm] "0402 from SM-752 data"
  rect 0.8x0.6 smd: 1(-0.6,0) 2(0.6,0)
  silkscreen extent -1.22,-0.52 1.22,0.52, body extent -0.55,-0.3 0.55,0.3, height 0.6
0603 [mm] "0603 from SM-752 data"
  rect 1x0.95 smd: 1(-0.8,0) 2(0.8,0)
  silkscreen extent -1.52,-0.69 1.52,0.69, body extent -0.87,-0.47 0.87,0.47, height 0.85
0805_HV [mil] "0805 with 30mil clearance between pads"
  rect 50x63 smd: 1(-40,0) 2(40,0)
  silkscreen extent -74,-40 74,40, body extent -43,-29 43,29, height 43
1206 [mm] "1206 from SM-752 data"
  rect 1.3x1.85 smd: 1(-1.45,0) 2(1.45,0)
  silkscreen extent -2.4,-1.21 2.4,1.21, body extent -1.7,-0.9 1.7,0.9, height 1.35
1210 [mm] "1210 from SM-752 data"
  rect 1.3x2.7 smd: 1(-1.45,0) 2(1.45,0)
  silkscreen extent -2.32,-1.57 2.32,1.57, body extent -1.7,-1.35 1.7,1.35, height 1.35
2220 [mm] "Chip Capacitor, Body 5.7x5.0mm, IPC Medium Density"
  rect 1.6x5.3 smd: 1(-2.6,0) 2(2.6,0)
  silkscreen extent -3.69,-2.94 3.69,2.94, body extent -2.95,-2.62 2.95,2.62, height 1.35
2512 [mm] "Chip Resistor, Body 6.3x3.2mm, IPC Medium Density"
  rect 1.3x3.4 smd: 1(-2.95,0) 2(2.95,0)
  silkscreen extent -1.9,-1.6 1.9,1.6, body extent -3.22,-1.67 3.22,1.67, height 0.71
AssemblyNote [mil] "Assembly Note"
CONN_SBH11-PBPC-D07-ST-BK [mm] "Sullins recommended land pattern"
  rect 1.65x1.65 hole 1.016 mask+0: 1(-7.62,-1.27)
  round 1.65 hole 1.016 mask+0: 2(-7.62,1.27) 3(-5.08,-1.27) 4(-5.08,1.27) 5(-2.54,-1.27) 6(-2.54,1.27) 7(0,-1.27) 8(0,1.27) 9(2.54,-1.27) 10(2.54,1.27) 11(5.08,-1.27) 12(5.08,1.27) 13(7.62,-1.27) 14(7.62,1.27)
  silkscreen extent -12.64,-5.08 12.64,4.7, body extent -12.64,-4.4 12.64,4.7, height 9.12
CUI_PJ-002AH-SMT [mm] "CUI"
  rect 2.8x2.4 smd: 1(-3.05,5.7) 1A(3.05,5.7) 2(-3.05,-5.7) 3(3.05,-5.7)
  round 1 hole 1.6 unplated: MH1(-3.05,0)
  round 1.524 hole 1.8 unplated: MH2(1.45,0)
  silkscreen extent -8.05,-4.5 6.75,5.45, body extent -8.05,-6.3 6.75,6.3, height 11.2
DDA0008E_N [mm]
  oval 2x0.6 smd: 1(-2.5,1.905) 2(-2.5,0.635) 3(-2.5,-0.635) 4(-2.5,-1.905) 5(2.5,-1.905) 6(2.5,-0.635) 7(2.5,0.635) 8(2.5,1.905)
  rect 2.4x3.1 smd: 9(0,0)
  silkscreen extent -3.22,-2.5 1.15,2.5, body extent -2.98,-2.45 2.98,2.45, height 1.5
DLW5BT_TQ2 [mm] "SMD, 4-Leads, Body 5x5mm"
  rect 0.5x0.5 smd: 1(-1,1.2) 2(-1,-1.2) 3(1,-1.2) 4(1,1.2)
  Layer 1 - Top Layer region: -0.45,2.35 -0.45,0.65 -1.45,0.65 -1.45,1.65 -2.75,1.65 -2.75,2.35
  Layer 1 - Top Layer region: 0.45,2.35 0.45,0.65 1.45,0.65 1.45,1.65 2.75,1.65 2.75,2.35
  Layer 1 - Top Layer region: -0.45,-2.35 -0.45,-0.65 -1.45,-0.65 -1.45,-1.65 -2.75,-1.65 -2.75,-2.35
  Layer 1 - Top Layer region: 0.45,-2.35 0.45,-0.65 1.45,-0.65 1.45,-1.65 2.75,-1.65 2.75,-2.35
  silkscreen extent -3.22,-2.65 2.65,2.65, body extent -2.65,-2.65 2.65,2.65, height 2.51
DMF_2100x1400 [mm] "Electrical  Double Layer Capacitor, Body 21.5x14.5mm, Pitch 3.5mm"
  rect 3.5x2.5 smd: 1(-14.25,3.5) 2(-14.25,-3.5) 3(-14.25,0)
  silkscreen extent -10.75,-7.25 10.75,7.25, body extent -14.75,-7.25 10.75,7.25, height 3.2
DPY0002A [mm] "R-PX2SON-N2"
  rect 0.6x0.5 smd: 1(-0.5,0) 2(0.5,0)
  body extent -0.55,-0.35 0.55,0.35, height 0.4
DQD0012A [mm] "SON, 12-Leads, Body 1.35x2.5mm, Pitch 0.4mm, Thermal Pad 2x0.4mm, TI Recommended"
  rect 0.45x0.2 smd mask+0.025: 1(-0.65,1) 2(-0.65,0.6) 3(-0.65,0.2) 4(-0.65,-0.2) 5(-0.65,-0.6) 6(-0.65,-1) 7(0.65,-1) 8(0.65,-0.6) 9(0.65,-0.2) 10(0.65,0.2) 11(0.65,0.6) 12(0.65,1)
  rect 0.4x2 smd paste-0.2 mask+0.025: 13(0,0)
  silkscreen extent -0.92,-1.45 0.72,1.45, body extent -0.72,-1.3 0.72,1.3, height 0.81
FCC_disclaimer_stacked [mil]
Fiducial10-20 [mm]
  round 1 smd mask+0.5: 1(0,0)
"GW CSSRM1_PC_White" [mm] "SMD, 3-Leads, Body 3x3mm, Pitch 1.1mm"
  rect 2.8x0.55 smd paste-0.3 mask-0.3: 1(0,1.125) 2(0,-1.125)
  rect 2.8x1 smd paste-0.5 mask-0.5: 3(0,0)
  silkscreen extent -1.8,-1.95 1.8,1.55, body extent -1.55,-1.55 1.55,1.55, height 2.35
IEC_Caution_Small [mil]
  silkscreen extent -107,-93 107,92
IEC_HighVoltage_Small [mil]
  silkscreen extent -107,-88 107,97
IEC_HotSurface_Small [mil]
  silkscreen extent -107,-93 107,92
Keystone5001 [mil] "For Keystone 500x miniature loop terminals"
  round 80 hole 40: 1(0,0)
  silkscreen extent -58,-58 58,58, body extent -49,-49 49,49, height 182
Keystone5002 [mil] "For Keystone 500x miniature loop terminals"
  round 80 hole 40: 1(0,0)
  silkscreen extent -58,-58 58,58, body extent -49,-49 49,49, height 182
Keystone5003 [mil] "For Keystone 500x miniature loop terminals"
  round 80 hole 40: 1(0,0)
  silkscreen extent -58,-58 58,58, body extent -49,-49 49,49, height 182
Keystone5004 [mil] "For Keystone 500x miniature loop terminals"
  round 80 hole 40: 1(0,0)
  silkscreen extent -58,-58 58,58, body extent -49,-49 49,49, height 182
Keystone_1902C [mil] "Hex Standoff, 4-40 threaded, nylon"
  body extent -145,-126 146,126, height 501
MC_CM8V-T1A [mm] "Micro Crystal AG"
  rect 0.8x1.5 smd: 1(-0.75,0) 2(0.75,0)
  silkscreen extent -1.03,-0.6 0.13,1.13, body extent -1,-0.6 1,0.6, height 0.6
Mill-Max_800-10-002-10-001000 [mm] "Mill-Max"
  rect 1.5x1.5 hole 0.85: 1(-1.27,0)
  round 1.5 hole 0.85: 2(1.27,0)
  silkscreen extent -2.54,-1.27 2.54,1.78, body extent -2.54,-1.27 2.54,1.27, height 8.13
Mill-Max_800-10-003-10-001000 [mm] "Mill-Max"
  rect 1.5x1.5 hole 0.85: 1(-2.54,0)
  round 1.5 hole 0.85: 2(0,0) 3(2.54,0)
  silkscreen extent -3.81,-1.27 3.81,1.78, body extent -3.81,-1.27 3.81,1.27, height 8.13
Molex_502774-0891 [mm] "SMD, 14-Leads, Body 15x14.3mm, Pitch 1.1mm"
  rect 0.8x1.68 smd mask+0.025: 1(-2.9,7.385) 2(-1.8,7.385) 3(-0.7,7.385) 4(0.4,7.385) 5(1.5,7.385) 6(2.6,7.385) 7(3.7,7.385) 8(4.8,7.385)
  rect 1.6x1.5 smd mask+0.025: 9(6.21,7.475)
  rect 1.29x1.3 smd mask+0.025: 10(6.855,5.825)
  rect 1.29x1.4 smd mask+0.025: 11(6.855,-1.575)
  rect 1.5x1.7 smd mask+0.025: 12(6.75,-7.375) 13(-6.75,-7.375)
  rect 1.7x1.5 smd mask+0.025: 14(-6.45,7.475)
  silkscreen extent -7.15,-7.88 7.15,8.9, body extent -7.15,-8 7.15,8, height 1.78
NDK_NX3225GD [mm] "NDK"
  rect 1.5x2.7 smd: 1(-0.95,0) 2(0.95,0)
  silkscreen extent -0.13,-1.58 0.1,1.58, body extent -1.65,-1.3 1.65,1.3, height 1
NHU0020A [mm] "QFN, 20-Leads, Body 2.5x3 mm, Pitch 0.4mm"
  rrect50% 0.6x0.2 smd mask+0.025: 1(-1.15,0.8) 2(-1.15,0.4) 3(-1.15,0) 4(-1.15,-0.4) 5(-1.15,-0.8) 11(1.15,-0.8) 12(1.15,-0.4) 13(1.15,0) 14(1.15,0.4) 15(1.15,0.8)
  rrect50% 0.2x0.6 smd mask+0.025: 6(-0.8,-1.4) 7(-0.4,-1.4) 8(0,-1.4) 9(0.4,-1.4) 10(0.8,-1.4) 16(0.8,1.4) 17(0.4,1.4) 18(0,1.4) 19(-0.4,1.4) 20(-0.8,1.4)
  rrect9% 1.1x1.6 smd paste-1.6 mask+0.025: 21(0,0)
  silkscreen extent -1.5,-1.8 1.5,1.8, body extent -1.25,-1.5 1.25,1.5, height 0.61
"NY PMS 440 0025 PH" [mm] "4-40 nylon screw and mounting hole"
  round 8 hole 3.2: 1(0,0)
  body extent -3.3,-3.3 3.3,3.3, height 2.69
Pb-Free_Overlay_Small [mil]
  silkscreen extent -46,-46 46,46
PhoenixContact_1715721 [mm] "Phoenix Contact 1715721 used on LM3445 design from Longmont"
  rect 1.905x1.905 hole 1.3: 1(-2.54,0)
  round 1.9 hole 1.3: 2(2.54,0)
  silkscreen extent -5.97,-4.75 5.28,5.36, body extent -5.82,-4.6 5.08,5.2, height 14.2
PW0014A_N [mm] "TSOP, 14-Leads, Body 5x4.4mm, Pitch 0.65mm, IPC Medium Density"
  oval 1.7x0.35 smd: 1(-2.85,1.95) 2(-2.85,1.3) 3(-2.85,0.65) 4(-2.85,0) 5(-2.85,-0.65) 6(-2.85,-1.3) 7(-2.85,-1.95) 8(2.85,-1.95) 9(2.85,-1.3) 10(2.85,-0.65) 11(2.85,0) 12(2.85,0.65) 13(2.85,1.3) 14(2.85,1.95)
  silkscreen extent -1.7,-2.55 1.7,2.55, body extent -3.21,-2.5 3.21,2.5, height 0.98
RGP0020D [mm] "QFN, 20-Leads, Body 4x4mm, Pitch 0.5mm, Thermal Pad 2.7x2.7mm, TI Recommended"
  oval 0.6x0.24 smd mask+0.025: 1(-1.9,1) 2(-1.9,0.5) 3(-1.9,0) 4(-1.9,-0.5) 5(-1.9,-1) 11(1.9,-1) 12(1.9,-0.5) 13(1.9,0) 14(1.9,0.5) 15(1.9,1)
  oval 0.24x0.6 smd mask+0.025: 6(-1,-1.9) 7(-0.5,-1.9) 8(0,-1.9) 9(0.5,-1.9) 10(1,-1.9) 16(1,1.9) 17(0.5,1.9) 18(0,1.9) 19(-0.5,1.9) 20(-1,1.9)
  rect 2.7x2.7 smd paste-1.35 mask+0.025: 21(0,0)
  silkscreen extent -2.22,-2.22 2.22,2.22, body extent -2.07,-2.07 2.07,2.07, height 1.01
RGZ0048B [mm] "QFN, 48-Leads, Body 7x7mm, Pitch 0.5mm, Thermal Pad 5.15x5.15mm, TI Recommended"
  oval 0.6x0.24 smd mask+0.051: 1(-3.4,2.75) 2(-3.4,2.25) 3(-3.4,1.75) 4(-3.4,1.25) 5(-3.4,0.75) 6(-3.4,0.25) 7(-3.4,-0.25) 8(-3.4,-0.75) 9(-3.4,-1.25) 10(-3.4,-1.75) 11(-3.4,-2.25) 12(-3.4,-2.75) 25(3.4,-2.75) 26(3.4,-2.25) 27(3.4,-1.75) 28(3.4,-1.25) 29(3.4,-0.75) 30(3.4,-0.25) 31(3.4,0.25) 32(3.4,0.75) 33(3.4,1.25) 34(3.4,1.75) 35(3.4,2.25) 36(3.4,2.75)
  oval 0.24x0.6 smd mask+0.051: 13(-2.75,-3.4) 14(-2.25,-3.4) 15(-1.75,-3.4) 16(-1.25,-3.4) 17(-0.75,-3.4) 18(-0.25,-3.4) 19(0.25,-3.4) 20(0.75,-3.4) 21(1.25,-3.4) 22(1.75,-3.4) 23(2.25,-3.4) 24(2.75,-3.4) 37(2.75,3.4) 38(2.25,3.4) 39(1.75,3.4) 40(1.25,3.4) 41(0.75,3.4) 42(0.25,3.4) 43(-0.25,3.4) 44(-0.75,3.4) 45(-1.25,3.4) 46(-1.75,3.4) 47(-2.25,3.4) 48(-2.75,3.4)
  rect 4.1x4.1 smd paste-2.575 mask+0.051: 49(0,0)
  silkscreen extent -3.72,-3.72 3.72,3.72, body extent -3.57,-3.58 3.58,3.57, height 1.01
SMA [mm] "Molded Diode, 2-Leads, Body 4.3x2.6mm, IPC Medium Density, based on OnSemi component dimensions and land pattern"
  rect 2x2 smd: 1(-2,0) 2(2,0)
  silkscreen extent -3.66,-1.57 2.79,1.57, body extent -2.6,-1.3 2.6,1.3, height 2.42
SMB [mil] "Molded Diode, 2-Leads, Body 5.4x3.6mm, IPC Medium Density, based on OnSemi component dimensions"
  rect 85x107.99 smd: 1(-87.01,0) 2(87.01,0)
  silkscreen extent -155,-82 125,82, body extent -106,-71 106,71, height 91
SMC [mil] "Molded Diode, 2-Leads, Body 6.9x5.8mm, IPC Medium Density, based on OnSemi component dimensions and land patterns"
  rect 110x150 smd: 1(-140.49,0) 2(140.49,0)
  silkscreen extent -221,-124 189,123, body extent -156,-116 156,116, height 91
SML-P1_RED [mm] "ROHM"
  rect 0.5x0.6 smd: 1(-0.45,0) 2(0.45,0)
  silkscreen extent -0.95,-0.3 -0.95,0.3, body extent -0.52,-0.33 0.52,0.33, height 0.25
SRP7030F_3 [mm] "BOURNS"
  rect 2.4x2.5 smd: 1(-3.1,0) 2(3,0)
  silkscreen extent -3.4,-3.4 3.4,3.4, body extent -3.35,-3.35 3.35,3.35, height 3
SW_FSM4JSMA [mm] "Alcoswitch"
  rect 1.4x2.1 smd: 1(2.25,4.55) 2(2.25,-4.55) 3(-2.25,4.55) 4(-2.25,-4.55)
  silkscreen extent -3,-3 3,5.4, body extent -3,-5 3,5, height 5.1
TI_Stacked_Overlay_Small [mil]
  silkscreen extent -418,-98 418,98
TRANS_NexFET_Q2 [mm] "TI recommended land pattern M0167-01"
  rect 0.46x0.4 smd mask+0: 1(-0.93,0.65) 2(-0.93,0) 3(-0.93,-0.65) 4(0.93,-0.65) 5(0.93,0) 6(0.93,0.65)
  rect 0.85x0.4 smd paste-0.025 mask+0: 7(0.095,-0.65)
  rect 1.1x1.05 smd paste-0.05 mask+0: 8(0,0.325)
  silkscreen extent -1.43,-1.12 1.43,1.12, body extent -1,-1 1,1, height 0.85
XFL4020 [mm] "Coilcraft XFL4020 7/18/12"
  rect 0.98x3.4 smd: 1(-1.181,0) 2(1.181,0)
  silkscreen extent -2.16,-2.16 2.16,2.16, body extent -2.15,-2.15 2.15,2.15, height 2.1

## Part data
C1 C5 C29 C33 C35 C36: "CAP, CERM, 0.1 µF, 50 V, +/- 10%, X7R, 0402"
C2 C3: "CAP, CERM, 4.7 µF, 50 V, +/- 10%, X7R, 1206"
C4: "CAP, CERM, 1000 pF, 2000 V, +/- 10%, X7R, 1210"
C6 C7: "CAP, CERM, 47 µF, 10 V, +/- 10%, X7R, 1210"
C8: "CAP, CERM, 0.082 µF, 16 V, +/- 10%, X7R, 0402"
C9 C12: "CAP, CERM, 0.1uF, 16V, +/-10%, X7R, 0402"
C10 C13: "CAP, CERM, 1uF, 16V, +/-10%, X7R, 0603"
C11 C14: "CAP, CERM, 10 µF, 6.3 V, +/- 20%, X7R, 0805"
C15 C16 C19 C20: "CAP, CERM, 2200pF, 50V, +/-10%, X7R, 0402"
C17 C18: "CAP, CERM, 12 pF, 25 V, +/- 5%, C0G/NP0, 0402"
C21 C22: "CAP, CERM, 10 pF, 50 V, +/- 5%, C0G/NP0, 0402"
C23: "CAP, CERM, 4.7 µF, 10 V, +/- 20%, X7R, 0805"
C24: "CAP, Electric Double Layer, 470000uF, 4.2 V, +/- 20%, 0.045 ohm, Electrical  Double Layer Capacitor, Body 21.5x14.5mm, Pitch 3.5mm SMD"
C25: "CAP, CERM, 2.2 µF, 16 V, +/- 10%, X7R, 0805"
C26 C27 C38: "CAP, CERM, 1 µF, 16 V, +/- 10%, X7R, 0603"
C28 C31 C32: "CAP, CERM, 0.01 µF, 16 V, +/- 10%, X7R, 0402"
C30: "CAP, CERM, 0.1 µF, 250 V, +/- 10%, X7R, 1206"
C34: "CAP, CERM, 0.047 µF, 16 V, +/- 10%, X7R, 0402"
C37: "CAP, CERM, 1 µF, 250 V, +/- 10%, X7R, 2220"
D1: "Diode, Schottky, 40 V, 2 A, SMB"
D2: "Diode, TVS, Bi, 36 V, 400 W, SMA"
D3: "Diode, Schottky, 60 V, 5 A, SMC"
D4 D5: "LED, Neutral White, SMD"
D6: "LED, Red, SMD"
FID1 FID2 FID3 FID4 FID5 FID6: "Fiducial mark.  There is nothing to buy or mount."
H1 H2 H3 H4: "Machine Screw, Round, #4-40 x 1/4, Nylon, Philips panhead"
H5 H6 H7 H8: "Standoff, Hex, 0.5\"L #4-40 Nylon"
J1 J3 J6 J9 J10 J11 LS1: "Header, 100mil, 2x1, TH"
J2: "Power Jack, SMT"
J4: "Conn Term Block, 2POS, 5.08mm, TH"
J5: "Conncetor, micro SD Card, 1.1 mm, R/A, SMT"
J7: "Header, 3x1, 100mil, SMT"
J8: "Header (shrouded), 100 mil, 7x2, Gold plated, TH"
L1: "Inductor, Flat Wire, Powdered Iron, 4.7 µH, 5 A, 0.035 ohm, SMD"
L2: "Coupled inductor, 2.5 A, 0.034 ohm, SMD"
L3: "1.5A Ferrite Bead, 330 ohm @ 100MHz, SMD"
L4: "Inductor, Shielded, Composite, 4.7 µH, 2.7 A, 0.05 ohm, SMD"
Logo1: library part TI_Logo, "Texas Instrument Corporate Signature"
Logo2: library part Pb-Free
Logo3: library part FCC_disclaimer, "FCC_disclaimer"
LOGO4: library part IEC_HotSurface, "IEC 61010-1 Hot Surface Warning"
LOGO5: library part IEC_HighVoltage, "IEC 61010-1 High Voltage Warning"
Logo6: library part IEC_Caution, "IEC 61010-1 Caution Warning"
Q1 Q2: "MOSFET, N-CH, 20 V, 10 A, SON 2x2mm"
R1: "RES, 28.0 k, 1%, 0.063 W, 0402"
R2: "RES, 34.0 k, 1%, 0.063 W, 0402"
R3 R4 R5 R9 R12: "RES, 10.0 k, 1%, 0.063 W, 0402"
R6 R7 R10 R11: "RES, 47.5k ohm, 1%, 0.1W, 0603"
R8 R30 R31: "RES, 100 k, 1%, 0.063 W, 0402"
R13 R14 R32: "RES, 0 ohm, 5%, 0.063W, 0402"
R15 R16: "RES, 0, 5%, 1 W, 2512"
R17: "RES, 0, 5%, 0.1 W, 0603"
R18 R19: "RES, 0, 5%, 0.063 W, 0402"
R20 R21: "RES, 0.075, 1%, 0.5 W, 1206"
R22: "RES, 909 k, 1%, 0.063 W, 0402"
R23: "RES, 1.21 k, 1%, 0.063 W, 0402"
R24: "RES, 2.74 k, 1%, 0.063 W, 0402"
R25: "RES, 4.02 k, 1%, 0.063 W, 0402"
R26: "RES, 18.7 k, 1%, 0.063 W, 0402"
R27: "RES, 12.4 k, 1%, 0.063 W, 0402"
R28: "RES, 6.98 k, 1%, 0.063 W, 0402"
R29: "RES, 6.19 k, 1%, 0.063 W, 0402"
S1 S2 S3 S4: "Switch, Tactile, SPST-NO, 0.05A, 12V, SMT"
TP1 TP2: "Test Point, Miniature, Black, TH"
TP3 TP4 TP9 TP10: "Test Point, Miniature, Yellow, TH"
TP5 TP6 TP7 TP8: "Test Point, Miniature, Orange, TH"
TP11 TP12: "Test Point, Miniature, White, TH"
U1: "40 V, 3.5 A Simple Switcher, 2.2 Mhz Step-Down Regulator with 40 uA Quiescent Current, DDA0008E"
U2: "Mixed Signal Microcontroller, RGZ0048B"
U3 U4 U5 U6 U7 U8 U9 U10 U11: "ESD in 0402 Package with 10 pF Capacitance and 6 V Breakdown, 1 Channel, -40 to +125 degC, 2-pin X2SON (DPY), Green (RoHS & no Sb/Br)"
U12: "5A Flash LED Driver with Automatic VLED and ESR Detection for Mobile Camera Systems, NHU0020A"
U13: "Piezo Driver with Integrated Boost Converter, RGP0020D"
U14: "R-R Out Quad Op Amp, PW0014A"
U15: "EMI Filter for Display Interface, 6 Channels, -40 to +85 degC, 12-pin WSON (DQD), Green (RoHS & no Sb/Br)"
Y1: "Tuning Fork Crystal, 32.768kHz, 9pf, SMD"
Y2: "Crystal, 8MHz, 5pF, SMD"
ZZ1 ZZ2 ZZ3 ZZ4: library part AssemblyNote

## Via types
v1: diameter 20, hole 10, Layer 1 - Top Layer to Layer 4 - Bottom Layer, tented both sides, 305 vias
v2: diameter 19.68, hole 7.87, Layer 1 - Top Layer to Layer 4 - Bottom Layer, 17 vias
v3: diameter 19.68, hole 7.87, Layer 1 - Top Layer to Layer 4 - Bottom Layer, tented top, 6 vias

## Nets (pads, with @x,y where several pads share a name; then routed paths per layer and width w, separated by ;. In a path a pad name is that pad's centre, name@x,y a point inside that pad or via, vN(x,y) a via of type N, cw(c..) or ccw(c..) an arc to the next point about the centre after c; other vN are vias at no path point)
3V3: J1.2 J6.1 J9.1 J10.1
3V3_LED: C23.1 J9.2 U12.14 | length 90.6
  Layer 1 - Top Layer w7: C23.1@2335.37,639.72 2349.62,625.47 U12.14@2349.62,555
3V3_PIEZO: C28.1 C29.2 C38.1 J10.2 L4.2 R30.2 U13.2 U14.4 | length 318
  Layer 1 - Top Layer w8: 1135,2220 1145.32,2209.68 U13.2@1180.2,2209.68
  Layer 1 - Top Layer w12: v1(855,2060) U14.4@855,2117.8
  Layer 1 - Top Layer w20: R30.2@825,2473.63 v1(825,2520) ; C28.1@855,2023.63 v1(855,2060) ; v1(1115,2330) 1115,2291.5 C38.1@1121.5,2285 1113.62,2277.13 C29.2@1113.62,2235.96 1119.04,2235.96 1135,2220
  other v1: 1138.62,1850 1238.62,1850 1138.62,1900 1188.62,1900 1238.62,1900
A0_CLK: TP6.1 U2.11 U15.9 | length 1161.6
  Layer 1 - Top Layer w7: U2.11@536.15,2102.56 562.56,2102.56 600,2140 600,2180 v1(660,2240) ; U15.9@820.59,2647.13 1047.13,2647.13 TP6.1@1050,2650
  Layer 4 - Bottom Layer w7: v1(660,2240) 730,2310 730,2595 785,2650 TP6.1@1050,2650
A0_SIMO: TP7.1 U2.24 U15.11 | length 1711.9
  Layer 1 - Top Layer w7: v1(280,2255) 280,2220 294.02,2205.98 U2.24@294.02,2147.83 ; U15.11@820.59,2678.62 848.62,2678.62 920,2750 TP7.1@1150,2750
  Layer 4 - Bottom Layer w7: v1(280,2255) 505,2255 545,2215 745,2215 915,2385 915,2495 990,2570 1085,2570 1150,2635 TP7.1@1150,2750
A0_SOMI: TP8.1 U2.25 U15.8 | length 1602.8
  Layer 1 - Top Layer w7: v1(255,2225) 255,2200 268.43,2186.57 U2.25@268.43,2122.24 ; U15.8@820.59,2631.38 948.62,2631.38 1030,2550 TP8.1@1150,2550
  Layer 4 - Bottom Layer w7: v1(255,2225) 315,2225 330,2240 495,2240 540,2195 755,2195 935,2375 935,2485 1000,2550 TP8.1@1150,2550
A1_RX: R14.1 TP10.1 U2.21 | length 1053.8
  Layer 1 - Top Layer w7: U2.21@353.08,2147.83 353.08,2276.29 v1(361.79,2285)
  Layer 4 - Bottom Layer w7: v1(361.79,2285) 361.79,2736.79 560,2935 TP10.1@560,3000 595,3035 R14.1@595,3101.38
A1_TX: R13.1 TP9.1 U2.20 | length 1127.5
  Layer 1 - Top Layer w7: U2.20@372.76,2147.83 372.76,2265.98 v1(391.79,2285)
  Layer 4 - Bottom Layer w7: v1(391.79,2285) 391.79,2736.79 655,3000 TP9.1@710,3000 710,3096.38 R13.1@705,3101.38
AVCC: C9.2 C10.2 C11.1 L3.2 U2.48
  other v1: 520,1825
B0_SCL: R4.1 TP4.1 U2.32 U12.10 | length 4295.4
  Layer 1 - Top Layer w7: TP4.1@125,2000 195,2000 210.55,1984.45 U2.32@268.43,1984.45 ; U12.10@2420.49,541.22 2446.22,541.22 v1(2460,555)
  Layer 4 - Bottom Layer w7: TP4.1@125,2000 125,2073.62 R4.1@123.62,2075 155,2075 210,2130 450,2130 520,2060 520,1885 555,1850 925,1850 1055,1980 1880,1980 1970,1890 1970,1080 2005,1045 2460,1045 2510,995 2510,700 2460,650 v1(2460,555)
B0_SDA: R5.1 TP3.1 U2.31 U12.8 | length 4507
  Layer 1 - Top Layer w7: TP3.1@125,2200 125,2100 220.87,2004.13 U2.31@268.43,2004.13 ; U12.8@2420.49,509.72 v1(2470,509.72)
  Layer 4 - Bottom Layer w7: TP3.1@125,2200 123.62,2198.62 R5.1@123.62,2120 155,2120 180,2145 460,2145 535,2070 535,1895 560,1870 920,1870 1050,2000 1890,2000 1990,1900 1990,1090 2015,1065 2470,1065 2530,1005 2530,690 2485,645 2485,524.72 v1(2470,509.72)
BTN_AUDIO: C16.1 R7.1 S2.1 S2.2 U2.16 U3.1 | length 4430.9
  Layer 1 - Top Layer w7: U2.16@451.5,2147.83 451.5,2183.5 475,2207 v1(475,2215) ; v1(1567.19,113.48) 1622.44,113.48 S2.1@1622.44,471.75 ; S2.1@1623.58,470.43 1623.58,573.58 1650,600 1943.28,600 2095,751.72 v1(2095,1140)
  Layer 4 - Bottom Layer w7: v1(475,2215) 490,2215 595,2110 595,2025 635,1985 935,1985 1030,2080 1930,2080 2095,1915 v1(2095,1140) ; U3.1@1553.54,363.92 1553.54,327.85 1557.48,323.92 1557.48,281.79 1567.19,272.09 v1(1567.19,113.48)
BTN_GAIN: C19.1 R10.1 S3.1 S3.2 U2.17 U4.1 | length 4796.9
  Layer 1 - Top Layer w7: U2.17@431.82,2147.83 431.82,2206.82 v1(440,2215) ; v1(1172.19,112.19) 1227.44,112.19 S3.1@1227.44,470.45 ; S3.1@1228.58,469.13 1228.58,568.58 1280,620 1935,620 2065,750 v1(2065,1140)
  Layer 4 - Bottom Layer w7: v1(440,2215) 465,2190 490,2190 580,2100 580,2010 625,1965 940,1965 1035,2060 1920,2060 2065,1915 v1(2065,1140) ; U4.1@1158.54,362.62 1158.54,326.56 1162.48,322.62 1162.48,280.49 1172.19,270.79 v1(1172.19,112.19)
BTN_LED: C20.1 R11.1 S4.1 S4.2 U2.18 U5.1 | length 5170.4
  Layer 1 - Top Layer w7: v1(405,2215) 412.13,2207.87 U2.18@412.13,2147.83 ; v1(777.18,112.18) 832.44,112.18 S4.1@832.44,470.45 ; S4.1@833.58,469.13 833.58,568.58 905,640 1926.72,640 2035,748.28 v1(2035,1140)
  Layer 4 - Bottom Layer w7: v1(405,2215) 445,2175 480,2175 565,2090 565,1995 615,1945 945,1945 1040,2040 1910,2040 2035,1915 v1(2035,1140) ; U5.1@763.54,362.62 763.54,326.55 767.48,322.62 767.48,280.49 777.18,270.78 v1(777.18,112.18)
DETECT_SD: R8.1 U2.9 U15.7 | length 2064.4
  Layer 1 - Top Layer w7: U2.9@536.15,2063.19 588.19,2063.19 v1(620,2095) ; U15.7@820.59,2615.63 851.37,2615.63 867,2600 R8.1@871.38,2600 v1(871.38,2560)
  Layer 4 - Bottom Layer w7: v1(620,2095) 620,2050 635,2035 916.5,2035 1270,2388.5 1270,2730 1185,2815 1115,2815 1080,2780 1080,2720 1120,2680 1120,2635 1075,2590 901.38,2590 v1(871.38,2560)
DRV2700_FB: R22.1 R26.2 U13.3 | length 115.4
  Layer 1 - Top Layer w7: R22.1@1113.62,2140 R26.2@1113.62,2187.98 1115.64,2190 U13.3@1180.2,2190
DRV_EN: U2.4 U13.20 | length 1005.3
  Layer 1 - Top Layer w7: U2.4@536.15,1964.76 574.76,1964.76 v1(670,2060) ; v1(1185,2420) 1215.63,2389.37 U13.20@1215.63,2264.8
  Layer 4 - Bottom Layer w7: v1(670,2060) 760,2060 1050,2350 1095,2350 1165,2420 v1(1185,2420)
DRV_GAIN0: U2.6 U13.18 | length 1118.2
  Layer 1 - Top Layer w7: U2.6@536.15,2004.13 561.13,2004.13 645,2088 v1(645,2115) ; v1(1245,2420) 1255,2410 U13.18@1255,2264.8
  Layer 4 - Bottom Layer w7: v1(645,2115) 765,2115 1040,2390 1075,2390 1155,2470 1230,2470 1245,2455 v1(1245,2420)
DRV_GAIN1: U2.5 U13.19 | length 1059.4
  Layer 1 - Top Layer w7: U2.5@536.15,1984.45 564.45,1984.45 v1(670,2090) ; v1(1215,2420) 1235.32,2399.68 U13.19@1235.32,2264.8
  Layer 4 - Bottom Layer w7: v1(670,2090) 765,2090 1045,2370 1085,2370 1165,2450 1205,2450 1215,2440 v1(1215,2420)
DVCC: C12.2 C13.2 C14.1 J6.2 J7.2 L3.1 R4.2 R5.2 R6.2 R7.2 R8.2 R9.2 R10.2 R11.2 U2.37 U15.10 | length 5198.4
  Layer 1 - Top Layer w7: U15.10@820.59,2662.87 867.87,2662.87 v1(880,2675)
  Layer 1 - Top Layer w20: v1(918.62,2560) R8.2@918.62,2600
  Layer 3 - PWR w50: v1(670,272.62) 1560,272.62 1627.62,205 2515,205 2625,315 2625,890 v1(2560,955) 2325,1190 2325,1450 1885,1890 1670,1890 1580,1980 1580,2400 1495,2485
  Layer 4 - Bottom Layer w20: v1(65,2035) 76.38,2046.38 R4.2@76.38,2075 ; v1(65,2160) 76.38,2148.62 R5.2@76.38,2120 ; v1(1520,3160) R6.2@1563.5,3160 ; R9.2@2560,913.62 v1(2560,955)
  Layer 4 - Bottom Layer w30: v1(670,272.62) R11.2@712.36,272.62 ; v1(1065,272.62) R10.2@1107.36,272.62 ; v1(1460,273.92) R7.2@1502.36,273.92
  other v1: 79.58,1740 129.58,1740 179.58,1740 229.58,1740 285,1825
FET_CON: Q1.3 Q2.3 U12.4 | length 1377.4
  Layer 1 - Top Layer w7: U12.4@2381.12,464.45 2381.12,428.88 v1(2395,415)
  Layer 1 - Top Layer w15: Q2.3@2696.06,788.62 2728.62,788.62 v1(2740,800) ; Q1.3@2976.06,788.62 3008.62,788.62 v1(3020,800)
  Layer 4 - Bottom Layer w15: v1(2395,415) 2395,310 2415,290 2700,290 2720,310 2720,780 v1(2740,800) v1(3020,800)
